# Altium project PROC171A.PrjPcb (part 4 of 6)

## Sheet PROC171_Ehernet_PHY_1.SchDoc
size 431 x 279 mm; Date: Not shown in title block; ApprovedBy: Not shown in title block; CheckedBy: Not shown in title block; Author: Not shown in title block; CompanyName: Not shown in title block; Engineer: Not shown in title block; Organization: Not shown in title block; Address1: Not shown in title block; Address2: Not shown in title block; Address3: Not shown in title block; Address4: Not shown in title block; DocumentNumber: 17; Revision: Use project parameter SCH_Rev; SheetNumber: 17; SheetTotal: 27; PageSetup: Record=PageOptions¦CenterHorizontal=True¦CenterVertical=True¦PrintScale=1.00¦XCorrection=1.00¦YCorrection=1.00¦PrintKind=0¦BorderSize=5000000¦LeftOffset=0¦BottomOffset=0¦Orientation=2¦PaperLength=1000¦PaperWidth=1000¦Scale=100¦PaperSource=15¦PrintQuality=600¦MediaType=1¦DitherType=10¦PaperKind=Letter¦PrintScaleMode=1
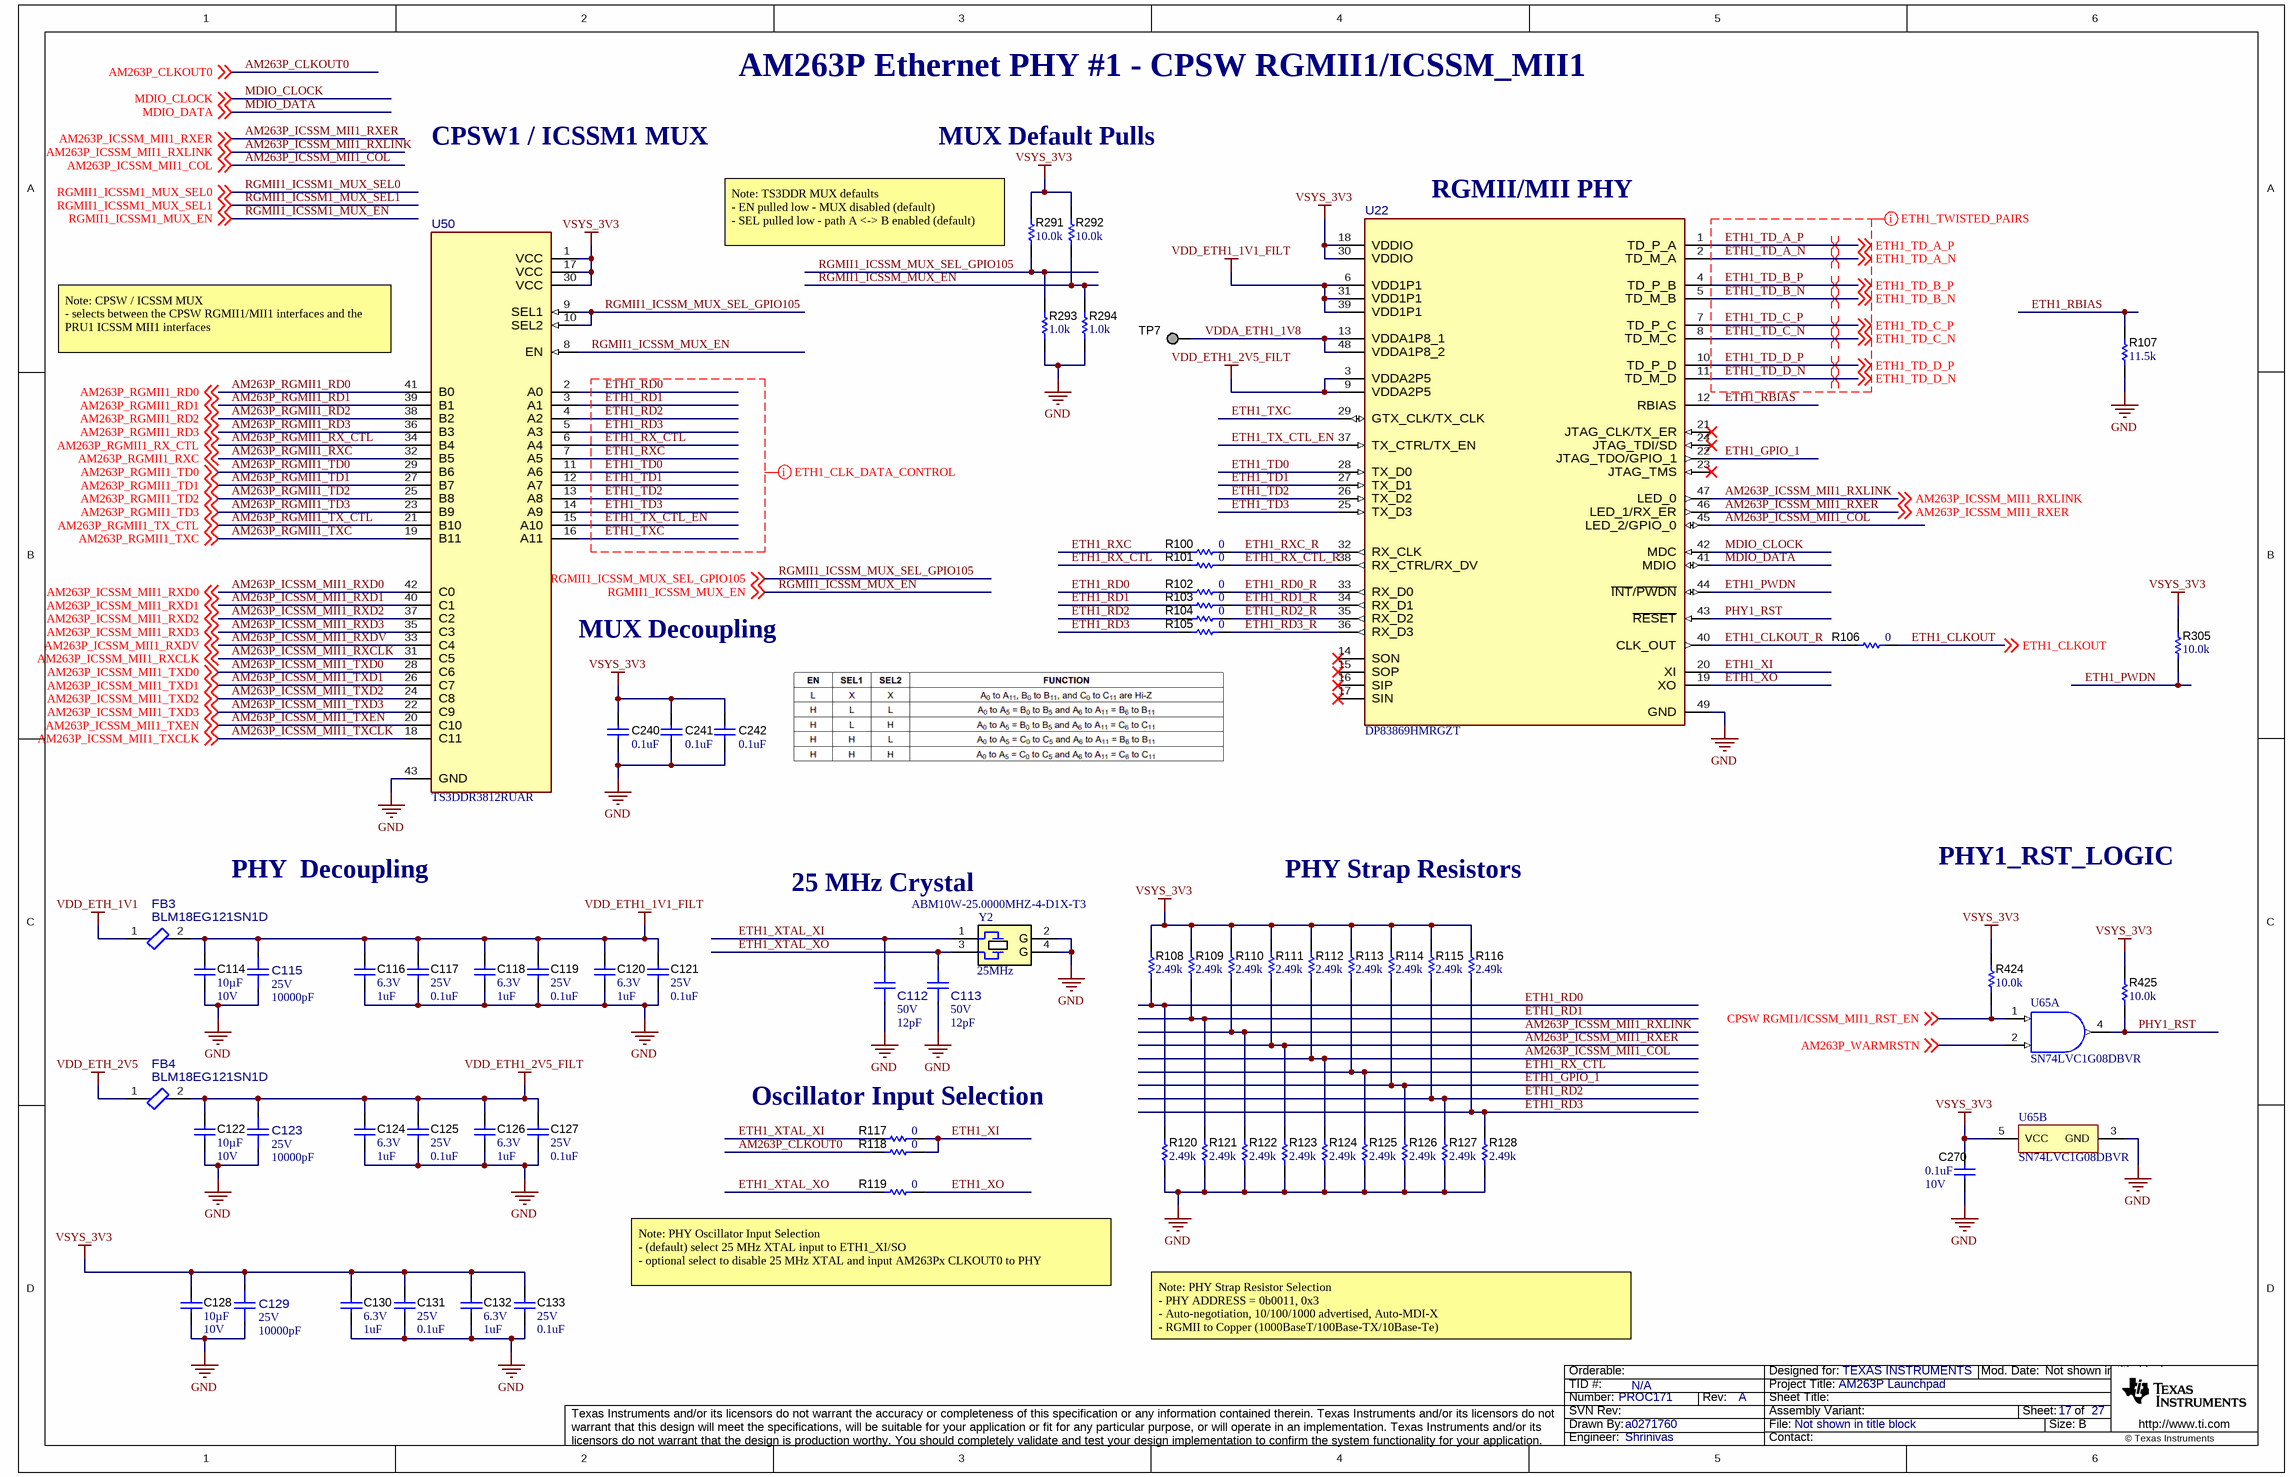
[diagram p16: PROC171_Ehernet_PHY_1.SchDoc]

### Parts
C112  VDC_V: 50V  ValueDisplayed: 12pF  [FP-GJM1555C1H120JB01D_0402-MFG]  (hidden comment: GJM1555C1H120JB01D)
C113  VDC_V: 50V  ValueDisplayed: 12pF  [FP-GJM1555C1H120JB01D_0402-MFG]  (hidden comment: GJM1555C1H120JB01D)
C114  Cap_F: 10µF  VDC_V: 10V  [0603]  (hidden comment: GRM188Z71A106MA73D)
C115  VDC_V: 25V  ValueDisplayed: 10000pF  [FP-GRM1555C1E103JE01D_0402-MFG]  (hidden comment: GRM1555C1E103JE01D)
C116  VDC_V: 6.3V  ValueDisplayed: 1uF  [0402]  (hidden comment: GRM155R70J105MA12D)
C117  VDC_V: 25V  ValueDisplayed: 0.1uF  [0402]  (hidden comment: GRM155R71E104KE14D)
C118  VDC_V: 6.3V  ValueDisplayed: 1uF  [0402]  (hidden comment: GRM155R70J105MA12D)
C119  VDC_V: 25V  ValueDisplayed: 0.1uF  [0402]  (hidden comment: GRM155R71E104KE14D)
C120  VDC_V: 6.3V  ValueDisplayed: 1uF  [0402]  (hidden comment: GRM155R70J105MA12D)
C121  VDC_V: 25V  ValueDisplayed: 0.1uF  [0402]  (hidden comment: GRM155R71E104KE14D)
C122  Cap_F: 10µF  VDC_V: 10V  [0603]  (hidden comment: GRM188Z71A106MA73D)
C123  VDC_V: 25V  ValueDisplayed: 10000pF  [FP-GRM1555C1E103JE01D_0402-MFG]  (hidden comment: GRM1555C1E103JE01D)
C124  VDC_V: 6.3V  ValueDisplayed: 1uF  [0402]  (hidden comment: GRM155R70J105MA12D)
C125  VDC_V: 25V  ValueDisplayed: 0.1uF  [0402]  (hidden comment: GRM155R71E104KE14D)
C126  VDC_V: 6.3V  ValueDisplayed: 1uF  [0402]  (hidden comment: GRM155R70J105MA12D)
C127  VDC_V: 25V  ValueDisplayed: 0.1uF  [0402]  (hidden comment: GRM155R71E104KE14D)
C128  Cap_F: 10µF  VDC_V: 10V  [0603]  (hidden comment: GRM188Z71A106MA73D)
C129  VDC_V: 25V  ValueDisplayed: 10000pF  [FP-GRM1555C1E103JE01D_0402-MFG]  (hidden comment: GRM1555C1E103JE01D)
C130  VDC_V: 6.3V  ValueDisplayed: 1uF  [0402]  (hidden comment: GRM155R70J105MA12D)
C131  VDC_V: 25V  ValueDisplayed: 0.1uF  [0402]  (hidden comment: GRM155R71E104KE14D)
C132  VDC_V: 6.3V  ValueDisplayed: 1uF  [0402]  (hidden comment: GRM155R70J105MA12D)
C133  VDC_V: 25V  ValueDisplayed: 0.1uF  [0402]  (hidden comment: GRM155R71E104KE14D)
C240  ValueDisplayed: 0.1uF  [0402]  (hidden comment: GRM155R71E104KE14D)
C241  ValueDisplayed: 0.1uF  [0402]  (hidden comment: GRM155R71E104KE14D)
C242  ValueDisplayed: 0.1uF  [0402]  (hidden comment: GRM155R71E104KE14D)
C270  VDC_V: 10V  ValueDisplayed: 0.1uF  [0402]  (hidden comment: 885012105010)
FB3  BLM18EG121SN1D  [FP-BLM18EG121SN1D_0603-MFG]
FB4  BLM18EG121SN1D  [FP-BLM18EG121SN1D_0603-MFG]
R100  ValueDisplayed: 0  [0402]  (hidden comment: ERJ-2GE0R00X)
R101  ValueDisplayed: 0  [0402]  (hidden comment: ERJ-2GE0R00X)
R102  ValueDisplayed: 0  [0402]  (hidden comment: ERJ-2GE0R00X)
R103  ValueDisplayed: 0  [0402]  (hidden comment: ERJ-2GE0R00X)
R104  ValueDisplayed: 0  [0402]  (hidden comment: ERJ-2GE0R00X)
R105  ValueDisplayed: 0  [0402]  (hidden comment: ERJ-2GE0R00X)
R106  ValueDisplayed: 0  [0402]  (hidden comment: ERJ-2GE0R00X)
R107  ValueDisplayed: 11.5k  [0402]  (hidden comment: ERJ-2RKF1152X)
R108  ValueDisplayed: 2.49k  [0402]  (hidden comment: CRCW04022K49FKED)
R109  ValueDisplayed: 2.49k  [0402]  (hidden comment: CRCW04022K49FKED)
R110  ValueDisplayed: 2.49k  [0402]  (hidden comment: CRCW04022K49FKED)
R111  ValueDisplayed: 2.49k  [0402]  (hidden comment: CRCW04022K49FKED)
R112  ValueDisplayed: 2.49k  [0402]  (hidden comment: CRCW04022K49FKED)
R113  ValueDisplayed: 2.49k  [0402]  (hidden comment: CRCW04022K49FKED)
R114  ValueDisplayed: 2.49k  [0402]  (hidden comment: CRCW04022K49FKED)
R115  ValueDisplayed: 2.49k  [0402]  (hidden comment: CRCW04022K49FKED)
R116  ValueDisplayed: 2.49k  [0402]  (hidden comment: CRCW04022K49FKED)
R117  ValueDisplayed: 0  [0402]  (hidden comment: ERJ-2GE0R00X)
R118  ValueDisplayed: 0  [0402]  (hidden comment: ERJ-2GE0R00X)
R119  ValueDisplayed: 0  [0402]  (hidden comment: ERJ-2GE0R00X)
R120  ValueDisplayed: 2.49k  [0402]  (hidden comment: CRCW04022K49FKED)
R121  ValueDisplayed: 2.49k  [0402]  (hidden comment: CRCW04022K49FKED)
R122  ValueDisplayed: 2.49k  [0402]  (hidden comment: CRCW04022K49FKED)
R123  ValueDisplayed: 2.49k  [0402]  (hidden comment: CRCW04022K49FKED)
R124  ValueDisplayed: 2.49k  [0402]  (hidden comment: CRCW04022K49FKED)
R125  ValueDisplayed: 2.49k  [0402]  (hidden comment: CRCW04022K49FKED)
R126  ValueDisplayed: 2.49k  [0402]  (hidden comment: CRCW04022K49FKED)
R127  ValueDisplayed: 2.49k  [0402]  (hidden comment: CRCW04022K49FKED)
R128  ValueDisplayed: 2.49k  [0402]  (hidden comment: CRCW04022K49FKED)
R291  ValueDisplayed: 10.0k  [0402]  (hidden comment: ERJ-2RKF1002X)
R292  ValueDisplayed: 10.0k  [0402]  (hidden comment: ERJ-2RKF1002X)
R293  ValueDisplayed: 1.0k  [0402]  (hidden comment: ERJ-2GEJ102X)
R294  ValueDisplayed: 1.0k  [0402]  (hidden comment: ERJ-2GEJ102X)
R305  ValueDisplayed: 10.0k  [0402]  (hidden comment: ERJ-2RKF1002X)
R424  ValueDisplayed: 10.0k  [0402]  (hidden comment: ERJ-2RKF1002X)
R425  ValueDisplayed: 10.0k  [0402L]  (hidden comment: CRCW040210K0FKED)
TP7  TESTPOINT  [TP_25MIL-SMT]  (value not drawn)  (no BOM)
U22  DP83869HMRGZT  [RGZ0048B-MFG]
U50  TS3DDR3812RUAR  [RUA0042A-MFG]
U65  SN74LVC1G08DBVR  [DBV0005A_N]  (parts A,B of 2)
Y2  Frequency_Fixed: 25MHz  [Abracon_ABM10W]  (hidden comment: ABM10W-25.0000MHZ-4-D1X-T3)

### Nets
GND: C112.1 C113.1 C114.2 C115.1 C116.2 C117.2 C118.2 C119.2 C120.2 C121.2 C122.2 C123.1 C124.2 C125.2 C126.2 C127.2 C128.2 C129.1 C130.2 C131.2 C132.2 C133.2 C240.1 C241.1 C242.1 C270.2 R107.1 R120.1 R121.1 R122.1 R123.1 R124.1 R125.1 R126.1 R127.1 R128.1 R293.1 R294.1 U22.49(GND) U50.43(GND) U65.3(GND) Y2.2(GND) Y2.4(GND)
VDD_ETH1_1V1_FILT: C114.1 C115.2 C116.1 C117.1 C118.1 C119.1 C120.1 C121.1 FB3.2 U22.6(VDD1P1) U22.31(VDD1P1) U22.39(VDD1P1)
VDD_ETH1_2V5_FILT: C122.1 C123.2 C124.1 C125.1 C126.1 C127.1 FB4.2 U22.3(VDDA2P5) U22.9(VDDA2P5)
VDD_ETH_1V1: FB3.1
VDD_ETH_2V5: FB4.1
VSYS_3V3: C128.1 C129.2 C130.1 C131.1 C132.1 C133.1 C240.2 C241.2 C242.2 C270.1 R108.2 R109.2 R110.2 R111.2 R112.2 R113.2 R114.2 R115.2 R116.2 R291.1 R292.1 R305.1 R424.1 R425.2 U22.18(VDDIO) U22.30(VDDIO) U50.1(VCC) U50.17(VCC) U50.30(VCC) U65.5(VCC)
AM263P_CLKOUT0: R118.1 ; off-sheet AM263P_CLKOUT0
AM263P_ICSSM_MII1_COL: R112.1 R124.2 U22.45(LED_2/GPIO_0) ; off-sheet AM263P_ICSSM_MII1_COL
AM263P_ICSSM_MII1_RXCLK: U50.31(C5) ; off-sheet AM263P_ICSSM_MII1_RXCLK
AM263P_ICSSM_MII1_RXD0: U50.42(C0) ; off-sheet AM263P_ICSSM_MII1_RXD0
AM263P_ICSSM_MII1_RXD1: U50.40(C1) ; off-sheet AM263P_ICSSM_MII1_RXD1
AM263P_ICSSM_MII1_RXD2: U50.37(C2) ; off-sheet AM263P_ICSSM_MII1_RXD2
AM263P_ICSSM_MII1_RXD3: U50.35(C3) ; off-sheet AM263P_ICSSM_MII1_RXD3
AM263P_ICSSM_MII1_RXDV: U50.33(C4) ; off-sheet AM263P_ICSSM_MII1_RXDV
AM263P_ICSSM_MII1_RXER: R111.1 R123.2 U22.46(LED_1/RX_ER) ; off-sheet AM263P_ICSSM_MII1_RXER
AM263P_ICSSM_MII1_RXLINK: R110.1 R122.2 U22.47(LED_0) ; off-sheet AM263P_ICSSM_MII1_RXLINK
AM263P_ICSSM_MII1_TXCLK: U50.18(C11) ; off-sheet AM263P_ICSSM_MII1_TXCLK
AM263P_ICSSM_MII1_TXD0: U50.28(C6) ; off-sheet AM263P_ICSSM_MII1_TXD0
AM263P_ICSSM_MII1_TXD1: U50.26(C7) ; off-sheet AM263P_ICSSM_MII1_TXD1
AM263P_ICSSM_MII1_TXD2: U50.24(C8) ; off-sheet AM263P_ICSSM_MII1_TXD2
AM263P_ICSSM_MII1_TXD3: U50.22(C9) ; off-sheet AM263P_ICSSM_MII1_TXD3
AM263P_ICSSM_MII1_TXEN: U50.20(C10) ; off-sheet AM263P_ICSSM_MII1_TXEN
AM263P_RGMII1_RD0: U50.41(B0) ; off-sheet AM263P_RGMII1_RD0
AM263P_RGMII1_RD1: U50.39(B1) ; off-sheet AM263P_RGMII1_RD1
AM263P_RGMII1_RD2: U50.38(B2) ; off-sheet AM263P_RGMII1_RD2
AM263P_RGMII1_RD3: U50.36(B3) ; off-sheet AM263P_RGMII1_RD3
AM263P_RGMII1_RX_CTL: U50.34(B4) ; off-sheet AM263P_RGMII1_RX_CTL
AM263P_RGMII1_RXC: U50.32(B5) ; off-sheet AM263P_RGMII1_RXC
AM263P_RGMII1_TD0: U50.29(B6) ; off-sheet AM263P_RGMII1_TD0
AM263P_RGMII1_TD1: U50.27(B7) ; off-sheet AM263P_RGMII1_TD1
AM263P_RGMII1_TD2: U50.25(B8) ; off-sheet AM263P_RGMII1_TD2
AM263P_RGMII1_TD3: U50.23(B9) ; off-sheet AM263P_RGMII1_TD3
AM263P_RGMII1_TX_CTL: U50.21(B10) ; off-sheet AM263P_RGMII1_TX_CTL
AM263P_RGMII1_TXC: U50.19(B11) ; off-sheet AM263P_RGMII1_TXC
AM263P_WARMRSTN: U65.2(B) ; off-sheet AM263P_WARMRSTN
CPSW RGMI1/ICSSM_MII1_RST_EN: R424.2 U65.1(A) ; off-sheet CPSW RGMI1/ICSSM_MII1_RST_EN
ETH1_CLKOUT: R106.2 ; off-sheet ETH1_CLKOUT
ETH1_CLKOUT_R: R106.1 U22.40(CLK_OUT)
ETH1_GPIO_1: R114.1 R126.2 U22.22(JTAG_TDO/GPIO_1)
ETH1_PWDN: R305.2 U22.44(~{INT}/~{PWDN})
ETH1_RBIAS: R107.2 U22.12(RBIAS)
ETH1_RD0: R102.1 R108.1 R120.2 U50.2(A0)
ETH1_RD0_R: R102.2 U22.33(RX_D0)
ETH1_RD1: R103.1 R109.1 R121.2 U50.3(A1)
ETH1_RD1_R: R103.2 U22.34(RX_D1)
ETH1_RD2: R104.1 R115.1 R127.2 U50.4(A2)
ETH1_RD2_R: R104.2 U22.35(RX_D2)
ETH1_RD3: R105.1 R116.1 R128.2 U50.5(A3)
ETH1_RD3_R: R105.2 U22.36(RX_D3)
ETH1_RX_CTL: R101.1 R113.1 R125.2 U50.6(A4)
ETH1_RX_CTL_R: R101.2 U22.38(RX_CTRL/RX_DV)
ETH1_RXC: R100.1 U50.7(A5)
ETH1_RXC_R: R100.2 U22.32(RX_CLK)
ETH1_TD0: U22.28(TX_D0) U50.11(A6)
ETH1_TD1: U22.27(TX_D1) U50.12(A7)
ETH1_TD2: U22.26(TX_D2) U50.13(A8)
ETH1_TD3: U22.25(TX_D3) U50.14(A9)
ETH1_TD_A_N: U22.2(TD_M_A) ; off-sheet ETH1_TD_A_N
ETH1_TD_A_P: U22.1(TD_P_A) ; off-sheet ETH1_TD_A_P
ETH1_TD_B_N: U22.5(TD_M_B) ; off-sheet ETH1_TD_B_N
ETH1_TD_B_P: U22.4(TD_P_B) ; off-sheet ETH1_TD_B_P
ETH1_TD_C_N: U22.8(TD_M_C) ; off-sheet ETH1_TD_C_N
ETH1_TD_C_P: U22.7(TD_P_C) ; off-sheet ETH1_TD_C_P
ETH1_TD_D_N: U22.11(TD_M_D) ; off-sheet ETH1_TD_D_N
ETH1_TD_D_P: U22.10(TD_P_D) ; off-sheet ETH1_TD_D_P
ETH1_TX_CTL_EN: U22.37(TX_CTRL/TX_EN) U50.15(A10)
ETH1_TXC: U22.29(GTX_CLK/TX_CLK) U50.16(A11)
ETH1_XI: R117.2 R118.2 U22.20(XI)
ETH1_XO: R119.2 U22.19(XO)
ETH1_XTAL_XI: C112.2 R117.1 Y2.1
ETH1_XTAL_XO: C113.2 R119.1 Y2.3
MDIO_CLOCK: U22.42(MDC) ; off-sheet MDIO_CLOCK
MDIO_DATA: U22.41(MDIO) ; off-sheet MDIO_DATA
PHY1_RST: R425.1 U22.43(~{RESET}) U65.4(Y)
RGMII1_ICSSM_MUX_EN: R292.2 R294.2 U50.8(EN) ; off-sheet RGMII1_ICSSM_MUX_EN
RGMII1_ICSSM_MUX_SEL_GPIO105: R291.2 R293.2 U50.9(SEL1) U50.10(SEL2) ; off-sheet RGMII1_ICSSM_MUX_SEL_GPIO105
VDDA_ETH1_1V8: TP7.1 U22.13(VDDA1P8_1) U22.48(VDDA1P8_2)

Not connected (* = marked no-connect by the designer): U22 14(SON)* 15(SOP)* 16(SIP)* 17(SIN)* 21(JTAG_CLK/TX_ER)* 23(JTAG_TMS)* 24(JTAG_TDI/SD)*

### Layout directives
differential pair: ETH1_TD_A_N, ETH1_TD_A_P, ETH1_TD_B_N, ETH1_TD_B_P, ETH1_TD_C_N, ETH1_TD_C_P, ETH1_TD_D_N, ETH1_TD_D_P
mark named ETH1_TWISTED_PAIRS: ETH1_TD_A_N, ETH1_TD_A_P, ETH1_TD_B_N, ETH1_TD_B_P, ETH1_TD_C_N, ETH1_TD_C_P, ETH1_TD_D_N, ETH1_TD_D_P
mark named ETH1_CLK_DATA_CONTROL: ETH1_RD0, ETH1_RD1, ETH1_RD2, ETH1_RD3, ETH1_RX_CTL, ETH1_RXC, ETH1_TD0, ETH1_TD1, ETH1_TD2, ETH1_TD3, ETH1_TX_CTL_EN, ETH1_TXC

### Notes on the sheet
- AM263P Ethernet PHY #1 - CPSW RGMII1/ICSSM_MII1
- CPSW1 / ICSSM1 MUX
- MUX Default Pulls
- (near U22) RGMII/MII PHY
- (near R291) Note: TS3DDR MUX defaults
  - EN pulled low - MUX disabled (default)
  - SEL pulled low - path A <-> B enabled (default)
- (near U50) Note: CPSW / ICSSM MUX
  - selects between the CPSW RGMII1/MII1 interfaces and the PRU1 ICSSM MII1 interfaces
- (near U50) MUX Decoupling
- PHY  Decoupling
- (near Y2) 25 MHz Crystal
- PHY Strap Resistors
- PHY1_RST_LOGIC
- Oscillator Input Selection
- (near R119) Note: PHY Oscillator Input Selection
  - (default) select 25 MHz XTAL input to ETH1_XI/SO
  - optional select to disable 25 MHz XTAL and input AM263Px CLKOUT0 to PHY
- Note: PHY Strap Resistor Selection
  - PHY ADDRESS = 0b0011, 0x3
  - Auto-negotiation, 10/100/1000 advertised, Auto-MDI-X
  - RGMII to Copper (1000BaseT/100Base-TX/10Base-Te)

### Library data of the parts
C112 C113 = CMP-0035228-1: Multi-Layer Ceramic Capacitor 12pF C0G  ±5% 0402 Paper T/R; Manufacturer: Murata; TempCo: 30ppm/°C; SizeZ_mm: 0.55mm; AEC Qualified: No
C114 C122 C128 = CMP-0007497-5: CAP, CERM, 10 uF, 10 V, +/- 20%, X7R, 0603; Manufacturer: MuRata; TaMin_C: -55°C; Polarized: N; SizeAreaWB_mm2: 4.68; Value1: Unknown; U/M: EA; Value: 10uF; TaMax_C: 125°C; SizeZ_mm: 1; SizeX_mm: 1.6; SizeY_mm: 0.8; SizeArea_mm2: 1.28; AEC Category: Q200
C115 C123 C129 = CMP-0035343-1: Chip Multilayer Ceramic Capacitors for General Purpose, 0402, 10000pF, C0G, 30ppm/°C, 5%, 25V; Manufacturer: Murata; Value: 10nF; SizeZ_mm: 0.65mm; AEC Qualified: No
C116 C118 C120 C124 C126 C130 C132 = CMP-0006624-2: CAP, CERM, 1 uF, 6.3 V, +/- 20%, X7R, 0402; Manufacturer: MuRata; TaMin_C: -55°C; Polarized: N; SizeAreaWB_mm2: 3; Value1: Unknown; U/M: EA; Value: 1uF; TaMax_C: 125°C; SizeZ_mm: 0.6; SizeX_mm: 1; SizeY_mm: 0.5; Cap_F: 1µF; AEC Category: Q200
C117 C119 C121 C125 C127 C131 C133 = CMP-0006659-2: CAP, CERM, 0.1 uF, 25 V, +/- 10%, X7R, 0402; Manufacturer: MuRata; TaMin_C: -55°C; Polarized: N; SizeAreaWB_mm2: 3; Value1: Unknown; U/M: EA; Value: 0.1uF; TaMax_C: 125°C; SizeZ_mm: 0.6; SizeX_mm: 1; SizeY_mm: 0.5; Cap_F: 100nF; AEC Category: Q200
C240-C242 = CMP-0006659-2: CAP, CERM, 0.1 uF, 25 V, +/- 10%, X7R, 0402; Manufacturer: MuRata; TaMin_C: -55°C; Polarized: N; SizeAreaWB_mm2: 3; U/M: EA; Value: 0.1uF; TaMax_C: 125°C; SizeZ_mm: 0.6; SizeX_mm: 1; SizeY_mm: 0.5; Value2: 25V; Cap_F: 100nF; AEC Category: Q200; Value1: Unknown
C270 = CMP-0006221-2: CAP, CERM, 0.1 uF, 10 V, +/- 20%, X5R, 0402; Manufacturer: Wurth Elektronik; TaMin_C: -55°C; Polarized: N; SizeAreaWB_mm2: 3; Value1: Unknown; U/M: EA; Value: 0.1uF; TaMax_C: 85°C; SizeZ_mm: 0.6; SizeX_mm: 1; SizeY_mm: 0.5; Cap_F: 100nF; AEC Category: Q200
FB3 FB4 = CMP-0089199-1: 120 Ohms @ 100MHz 1  Ferrite Bead 0603 (1608 Metric) 2A 40mOhm; Manufacturer: Murata; DCR_ohm: 60m; AEC Qualified: No; Tolerance_%: 25%; SizeZ_mm: 0.95mm; Impedance At Frequency: 120Ω @ 100MHz
R100-R106 R117-R119 = CMP-0026992-3: RES, 0, 5%, 0.1 W, AEC-Q200 Grade 0, 0402; Manufacturer: Panasonic; Power_W: 100mW; TempCo: 600 ppm/C; Value_Code: 0000; Value: 0; EIA_Code: E24; SizeX_mm: 1; SizeY_mm: 0.5; SizeZ_mm: 0.6; Value2: 0.1W; AEC Qualified: Y; VDC_V: 50V; AEC Category: Q200; SizeAreaWB_mm2: 3
R107 = CMP-0082348-1: RES, 11.5 k, 1%, 0.1 W, AEC-Q200 Grade 0, 0402; Manufacturer: Panasonic; Value_Code: 11k5; SizeAreaWB_mm2: 3; SizeArea_mm2: 0.5; AEC Qualified: Y; AEC Category: Q200; Value: 11.5k; SizeZ_mm: 0.6; EIA_Code: E96; TempCo: 100 ppm/C; AEC Grade: 0; Power_W: 100mW; Value2: 0.1W; SizeX_mm: 1
R108-R116 R120-R128 = CMP-0026237-2: RES, 2.49 k, 1%, 0.063 W, AEC-Q200 Grade 0, 0402; Manufacturer: Vishay-Dale; Power_W: 63mW; TempCo: 100 ppm/C; Value_Code: 2k49; Value: 2.49k; EIA_Code: E96; SizeX_mm: 1; SizeY_mm: 0.5; SizeZ_mm: 0.6; Value2: 0.063W; AEC Qualified: Y; VDC_V: 50V; AEC Category: Q200; AEC Grade: 0
R291 R292 R305 R424 = CMP-0026658-1: RES, 10.0 k, 1%, 0.1 W, 0402; Manufacturer: Panasonic; Power_W: 100mW; TempCo: 100 ppm/C; Value_Code: 10k0; U/M: EA; Value: 10.0k; EIA_Code: E96; Res_ohm: 10k; SizeX_mm: 1; SizeY_mm: 0.5; SizeZ_mm: 0.6; Value2: 0.1W; VDC_V: 50V; AEC Category: Q200
R293 R294 = CMP-0078193-1: RES, 1.0 k, 5%, 0.1 W, AEC-Q200 Grade 0, 0402; Manufacturer: Panasonic; Value_Code: 1k00; SizeArea_mm2: 0.5; AEC Qualified: Y; AEC Category: Q200; Res_ohm: 1k; Value: 1.0k; SizeZ_mm: 0.6; Green_REACh: Passed; EIA_Code: E24; TempCo: 200 ppm/C; AEC Grade: 0; Power_W: 100mW; VDC_V: 50V; Value2: 0.1W; Green_Lifecycle: Active; U/M: EA; SizeX_mm: 1
R425 = CMP-0025958-3: RES, 10.0 k, 1%, 0.063 W, AEC-Q200 Grade 0, 0402; Manufacturer: Vishay-Dale; Power_W: 63mW; TempCo: 100 ppm/C; Value_Code: 10k0; Value: 10.0k; EIA_Code: E96; Res_ohm: 10k; SizeX_mm: 1; SizeY_mm: 0.5; SizeZ_mm: 0.6; Value2: 0.063W; AEC Qualified: Y; VDC_V: 50V; AEC Category: Q200; AEC Grade: 0
TP7 = CMP-0078143-3: TEST POINT.  No entry in BOM.
U22 = CMP-0091377-1: 1/1 Transceiver Ethernet 48-VQFN (7x7); Manufacturer: Texas Instruments; TaMin_C: -40°C; SizeZ_mm: 1mm; TaMax_C: +125°C; Max Supply Voltage: 3.45V; Number Of Channels: 1; AEC Qualified: No; Data Rate: 1000Mbits/s; Min Supply Voltage: 990mV; Simplex Duplex: Full-Duplex; Standoff Height: 0mm
U50 = CMP-0093539-2: IC MUX/DEMUX DDR3 1:2 42WQFN; Manufacturer: Texas Instruments; TaMax_C: +85°C; TaMin_C: -40°C; On State Resistance: 8Ω; SizeZ_mm: 0.8mm; Min Supply Voltage: 3V; Standoff Height: 0mm; Max Supply Voltage: 3.6V; AEC Qualified: No; PositionCount: 12; -3Db Bandwith: 1.675GHz; Nominal Supply Current: 300uA; AEC Category: Q200
U65 = CMP-0051588-2: Single 2-Input Positive-AND Gate, DBV0005A, LARGE T&R; Manufacturer: Texas Instruments; Logic: True; ICC @ Nom Voltage(Max)(mA): 0.01; VCC(Min)(V): 1.65; Bits(#): 1; Rating: Catalog; Schmitt Trigger: No; Voltage(Nom)(V): 1.8,2.5,3.3,5; Output Drive (IOL/IOH)(Max)(mA): 32/-32; Gate Type: AND; tpd @ Nom Voltage(Max)(ns): 4.5,6,4,5; VCC(Max)(V): 5.5; Output Type: CMOS; F @ Nom Voltage(Max)(Mhz): 150; Input Type: CMOS/TTL; Technology Family: LVC; AEC Category: Q200; AEC Qualified: N; CompType: IC
Y2 = CMP-0084811-1: Crystal, 25 MHz, 10 ppm, 4 pF, SMD; Manufacturer: Abracon Corporation; Load Capacitance: 4 pF; TaMax_C: 85°C; SizeY_mm: 2.5; SizeAreaWB_mm2: 10.5; AEC Category: Q200; Frequency Stability: 20 ppm; SizeX_mm: 2; SizeArea_mm2: 5; SizeZ_mm: 0.6; AEC Qualified: N; TaMin_C: -40°C; Frequency Tolerance: 10 ppm

## Sheet PROC171_Ehernet_PHY_2.SchDoc
size 431 x 279 mm; Date: Not shown in title block; ApprovedBy: Not shown in title block; CheckedBy: Not shown in title block; Author: Not shown in title block; CompanyName: Not shown in title block; Engineer: Not shown in title block; Organization: Not shown in title block; Address1: Not shown in title block; Address2: Not shown in title block; Address3: Not shown in title block; Address4: Not shown in title block; DocumentNumber: 18; Revision: Use project parameter SCH_Rev; SheetNumber: 18; SheetTotal: 27; PageSetup: Record=PageOptions¦CenterHorizontal=True¦CenterVertical=True¦PrintScale=1.00¦XCorrection=1.00¦YCorrection=1.00¦PrintKind=0¦BorderSize=5000000¦LeftOffset=0¦BottomOffset=0¦Orientation=2¦PaperLength=1000¦PaperWidth=1000¦Scale=100¦PaperSource=15¦PrintQuality=600¦MediaType=1¦DitherType=10¦PaperKind=Letter¦PrintScaleMode=1
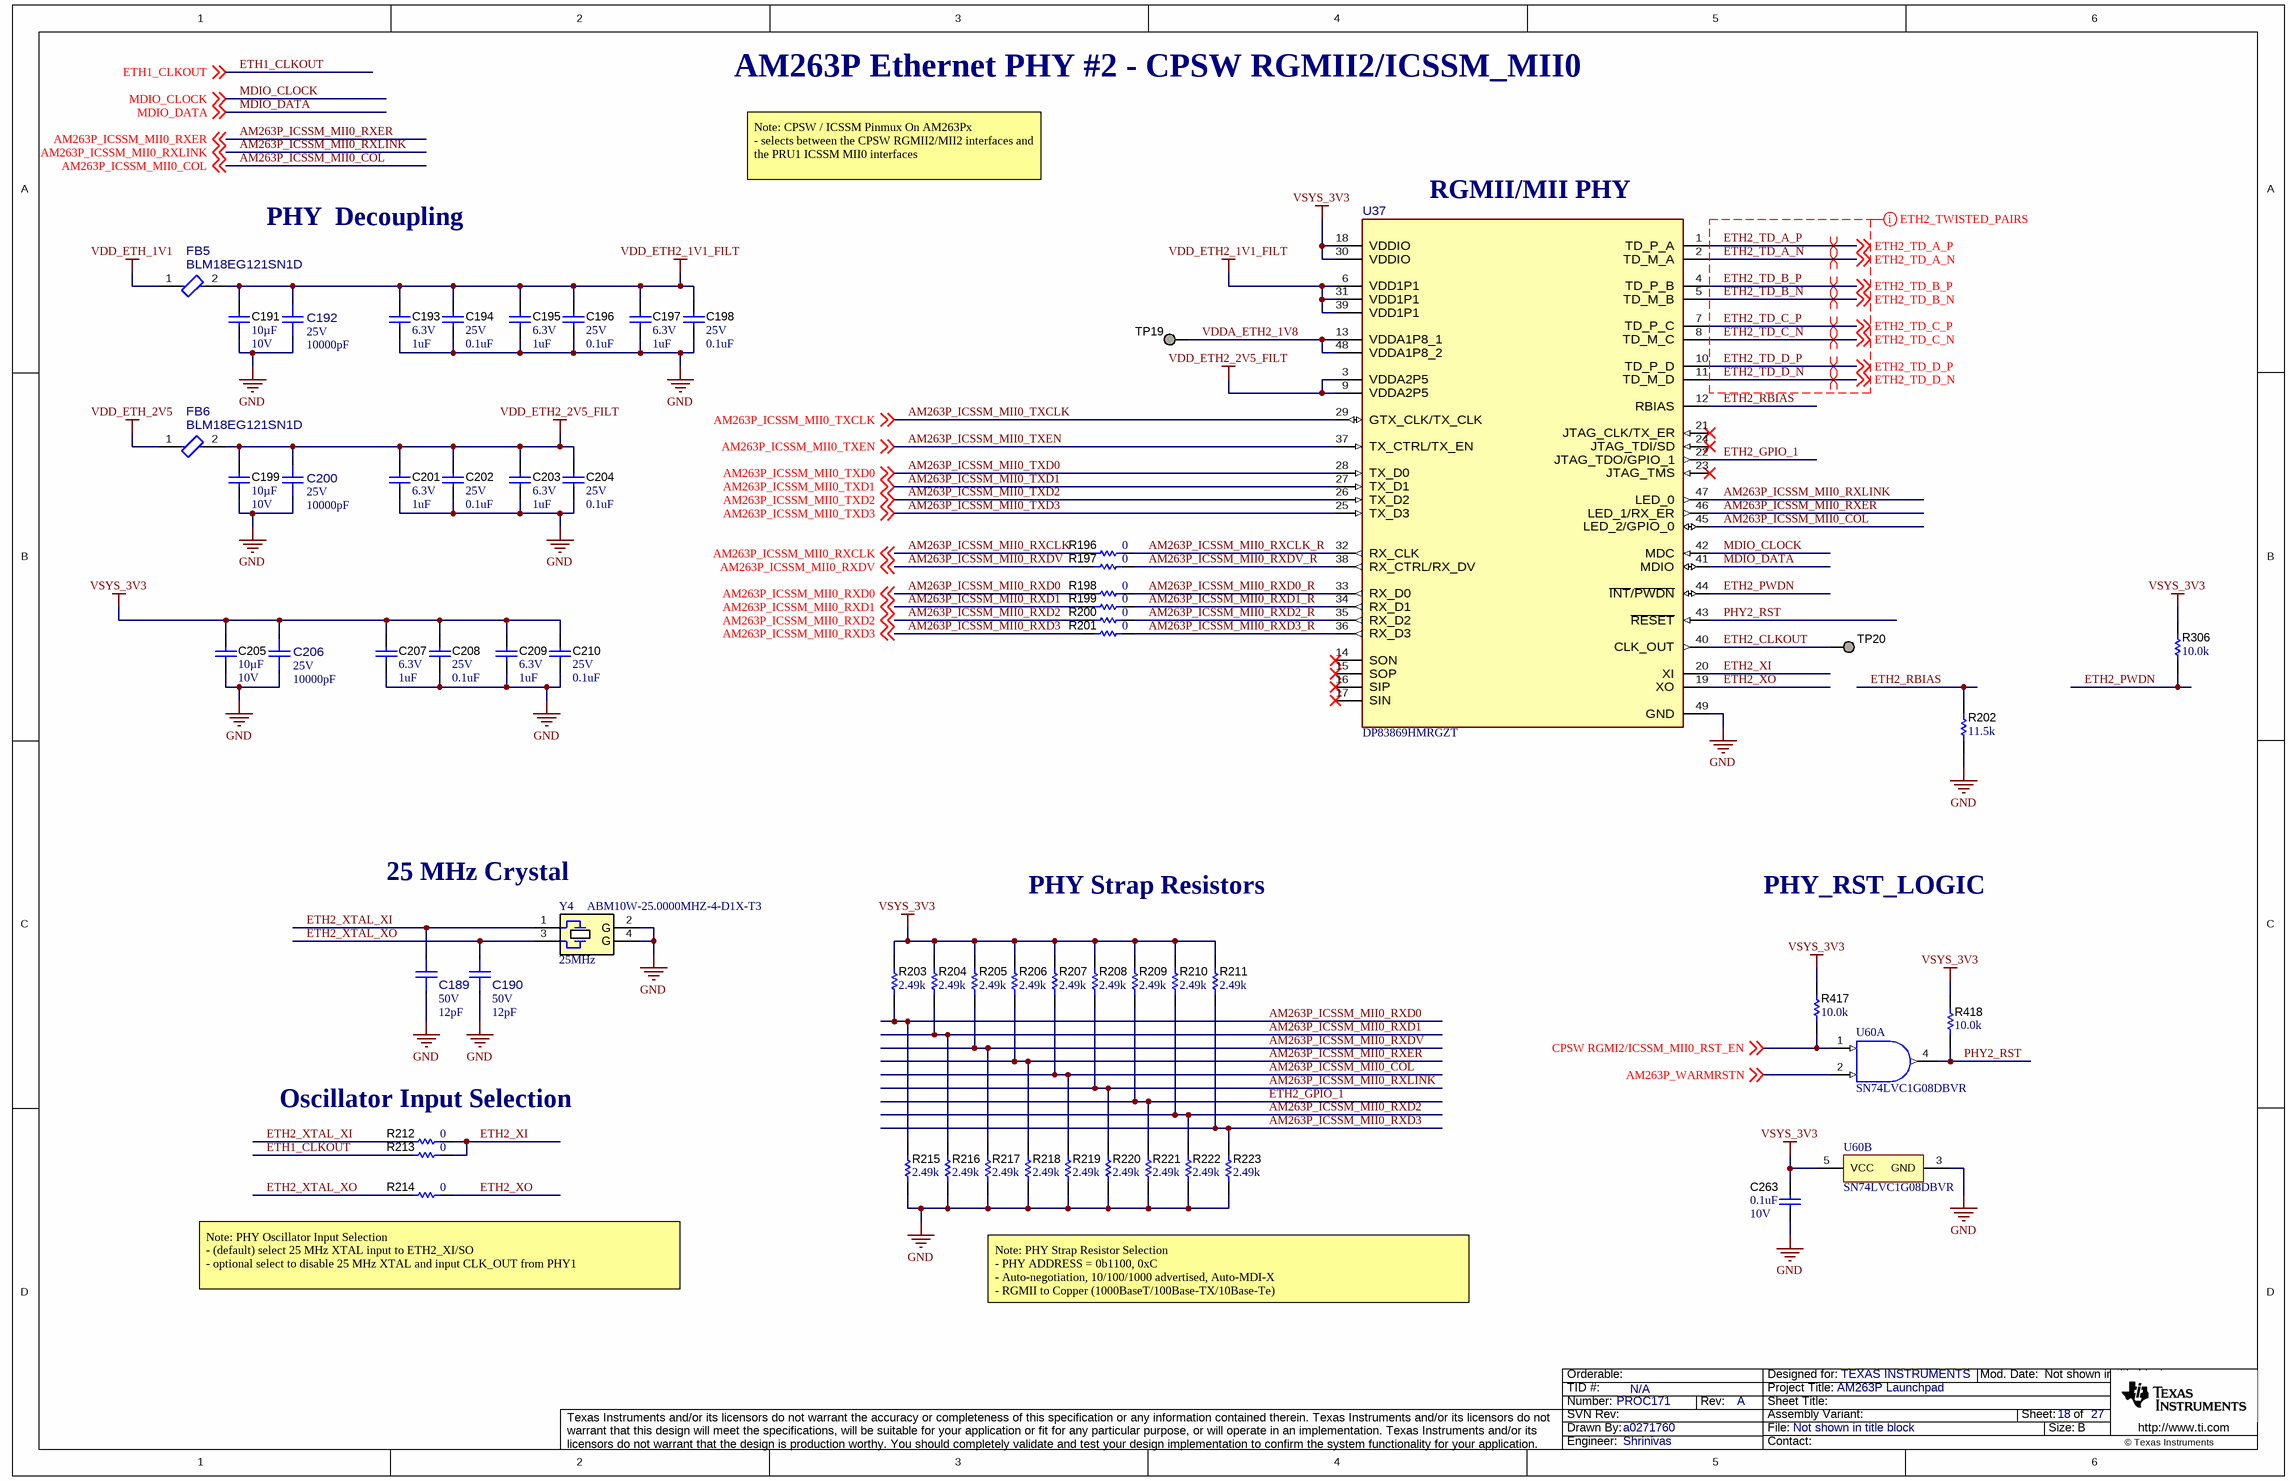
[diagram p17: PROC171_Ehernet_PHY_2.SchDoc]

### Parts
C189  VDC_V: 50V  ValueDisplayed: 12pF  [FP-GJM1555C1H120JB01D_0402-MFG]  (hidden comment: GJM1555C1H120JB01D)
C190  VDC_V: 50V  ValueDisplayed: 12pF  [FP-GJM1555C1H120JB01D_0402-MFG]  (hidden comment: GJM1555C1H120JB01D)
C191  Cap_F: 10µF  VDC_V: 10V  [0603]  (hidden comment: GRM188Z71A106MA73D)
C192  VDC_V: 25V  ValueDisplayed: 10000pF  [FP-GRM1555C1E103JE01D_0402-MFG]  (hidden comment: GRM1555C1E103JE01D)
C193  VDC_V: 6.3V  ValueDisplayed: 1uF  [0402]  (hidden comment: GRM155R70J105MA12D)
C194  VDC_V: 25V  ValueDisplayed: 0.1uF  [0402]  (hidden comment: GRM155R71E104KE14D)
C195  VDC_V: 6.3V  ValueDisplayed: 1uF  [0402]  (hidden comment: GRM155R70J105MA12D)
C196  VDC_V: 25V  ValueDisplayed: 0.1uF  [0402]  (hidden comment: GRM155R71E104KE14D)
C197  VDC_V: 6.3V  ValueDisplayed: 1uF  [0402]  (hidden comment: GRM155R70J105MA12D)
C198  VDC_V: 25V  ValueDisplayed: 0.1uF  [0402]  (hidden comment: GRM155R71E104KE14D)
C199  Cap_F: 10µF  VDC_V: 10V  [0603]  (hidden comment: GRM188Z71A106MA73D)
C200  VDC_V: 25V  ValueDisplayed: 10000pF  [FP-GRM1555C1E103JE01D_0402-MFG]  (hidden comment: GRM1555C1E103JE01D)
C201  VDC_V: 6.3V  ValueDisplayed: 1uF  [0402]  (hidden comment: GRM155R70J105MA12D)
C202  VDC_V: 25V  ValueDisplayed: 0.1uF  [0402]  (hidden comment: GRM155R71E104KE14D)
C203  VDC_V: 6.3V  ValueDisplayed: 1uF  [0402]  (hidden comment: GRM155R70J105MA12D)
C204  VDC_V: 25V  ValueDisplayed: 0.1uF  [0402]  (hidden comment: GRM155R71E104KE14D)
C205  Cap_F: 10µF  VDC_V: 10V  [0603]  (hidden comment: GRM188Z71A106MA73D)
C206  VDC_V: 25V  ValueDisplayed: 10000pF  [FP-GRM1555C1E103JE01D_0402-MFG]  (hidden comment: GRM1555C1E103JE01D)
C207  VDC_V: 6.3V  ValueDisplayed: 1uF  [0402]  (hidden comment: GRM155R70J105MA12D)
C208  VDC_V: 25V  ValueDisplayed: 0.1uF  [0402]  (hidden comment: GRM155R71E104KE14D)
C209  VDC_V: 6.3V  ValueDisplayed: 1uF  [0402]  (hidden comment: GRM155R70J105MA12D)
C210  VDC_V: 25V  ValueDisplayed: 0.1uF  [0402]  (hidden comment: GRM155R71E104KE14D)
C263  VDC_V: 10V  ValueDisplayed: 0.1uF  [0402]  (hidden comment: 885012105010)
FB5  BLM18EG121SN1D  [FP-BLM18EG121SN1D_0603-MFG]
FB6  BLM18EG121SN1D  [FP-BLM18EG121SN1D_0603-MFG]
R196  ValueDisplayed: 0  [0402]  (hidden comment: ERJ-2GE0R00X)
R197  ValueDisplayed: 0  [0402]  (hidden comment: ERJ-2GE0R00X)
R198  ValueDisplayed: 0  [0402]  (hidden comment: ERJ-2GE0R00X)
R199  ValueDisplayed: 0  [0402]  (hidden comment: ERJ-2GE0R00X)
R200  ValueDisplayed: 0  [0402]  (hidden comment: ERJ-2GE0R00X)
R201  ValueDisplayed: 0  [0402]  (hidden comment: ERJ-2GE0R00X)
R202  ValueDisplayed: 11.5k  [0402]  (hidden comment: ERJ-2RKF1152X)
R203  ValueDisplayed: 2.49k  [0402]  (hidden comment: CRCW04022K49FKED)
R204  ValueDisplayed: 2.49k  [0402]  (hidden comment: CRCW04022K49FKED)
R205  ValueDisplayed: 2.49k  [0402]  (hidden comment: CRCW04022K49FKED)
R206  ValueDisplayed: 2.49k  [0402]  (hidden comment: CRCW04022K49FKED)
R207  ValueDisplayed: 2.49k  [0402]  (hidden comment: CRCW04022K49FKED)
R208  ValueDisplayed: 2.49k  [0402]  (hidden comment: CRCW04022K49FKED)
R209  ValueDisplayed: 2.49k  [0402]  (hidden comment: CRCW04022K49FKED)
R210  ValueDisplayed: 2.49k  [0402]  (hidden comment: CRCW04022K49FKED)
R211  ValueDisplayed: 2.49k  [0402]  (hidden comment: CRCW04022K49FKED)
R212  ValueDisplayed: 0  [0402]  (hidden comment: ERJ-2GE0R00X)
R213  ValueDisplayed: 0  [0402]  (hidden comment: ERJ-2GE0R00X)
R214  ValueDisplayed: 0  [0402]  (hidden comment: ERJ-2GE0R00X)
R215  ValueDisplayed: 2.49k  [0402]  (hidden comment: CRCW04022K49FKED)
R216  ValueDisplayed: 2.49k  [0402]  (hidden comment: CRCW04022K49FKED)
R217  ValueDisplayed: 2.49k  [0402]  (hidden comment: CRCW04022K49FKED)
R218  ValueDisplayed: 2.49k  [0402]  (hidden comment: CRCW04022K49FKED)
R219  ValueDisplayed: 2.49k  [0402]  (hidden comment: CRCW04022K49FKED)
R220  ValueDisplayed: 2.49k  [0402]  (hidden comment: CRCW04022K49FKED)
R221  ValueDisplayed: 2.49k  [0402]  (hidden comment: CRCW04022K49FKED)
R222  ValueDisplayed: 2.49k  [0402]  (hidden comment: CRCW04022K49FKED)
R223  ValueDisplayed: 2.49k  [0402]  (hidden comment: CRCW04022K49FKED)
R306  ValueDisplayed: 10.0k  [0402]  (hidden comment: ERJ-2RKF1002X)
R417  ValueDisplayed: 10.0k  [0402]  (hidden comment: ERJ-2RKF1002X)
R418  ValueDisplayed: 10.0k  [0402L]  (hidden comment: CRCW040210K0FKED)
TP19  TESTPOINT  [TP_25MIL-SMT]  (value not drawn)  (no BOM)
TP20  TESTPOINT  [TP_25MIL-SMT]  (value not drawn)  (no BOM)
U37  DP83869HMRGZT  [RGZ0048B-MFG]
U60  SN74LVC1G08DBVR  [DBV0005A_N]  (parts A,B of 2)
Y4  Frequency_Fixed: 25MHz  [Abracon_ABM10W]  (hidden comment: ABM10W-25.0000MHZ-4-D1X-T3)

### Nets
GND: C189.1 C190.1 C191.2 C192.1 C193.2 C194.2 C195.2 C196.2 C197.2 C198.2 C199.2 C200.1 C201.2 C202.2 C203.2 C204.2 C205.2 C206.1 C207.2 C208.2 C209.2 C210.2 C263.2 R202.1 R215.1 R216.1 R217.1 R218.1 R219.1 R220.1 R221.1 R222.1 R223.1 U37.49(GND) U60.3(GND) Y4.2(GND) Y4.4(GND)
VDD_ETH2_1V1_FILT: C191.1 C192.2 C193.1 C194.1 C195.1 C196.1 C197.1 C198.1 FB5.2 U37.6(VDD1P1) U37.31(VDD1P1) U37.39(VDD1P1)
VDD_ETH2_2V5_FILT: C199.1 C200.2 C201.1 C202.1 C203.1 C204.1 FB6.2 U37.3(VDDA2P5) U37.9(VDDA2P5)
VDD_ETH_1V1: FB5.1
VDD_ETH_2V5: FB6.1
VSYS_3V3: C205.1 C206.2 C207.1 C208.1 C209.1 C210.1 C263.1 R203.2 R204.2 R205.2 R206.2 R207.2 R208.2 R209.2 R210.2 R211.2 R306.1 R417.1 R418.2 U37.18(VDDIO) U37.30(VDDIO) U60.5(VCC)
AM263P_ICSSM_MII0_COL: R207.1 R219.2 U37.45(LED_2/GPIO_0) ; off-sheet AM263P_ICSSM_MII0_COL
AM263P_ICSSM_MII0_RXCLK: R196.1 ; off-sheet AM263P_ICSSM_MII0_RXCLK
AM263P_ICSSM_MII0_RXCLK_R: R196.2 U37.32(RX_CLK)
AM263P_ICSSM_MII0_RXD0: R198.1 R203.1 R215.2 ; off-sheet AM263P_ICSSM_MII0_RXD0
AM263P_ICSSM_MII0_RXD0_R: R198.2 U37.33(RX_D0)
AM263P_ICSSM_MII0_RXD1: R199.1 R204.1 R216.2 ; off-sheet AM263P_ICSSM_MII0_RXD1
AM263P_ICSSM_MII0_RXD1_R: R199.2 U37.34(RX_D1)
AM263P_ICSSM_MII0_RXD2: R200.1 R210.1 R222.2 ; off-sheet AM263P_ICSSM_MII0_RXD2
AM263P_ICSSM_MII0_RXD2_R: R200.2 U37.35(RX_D2)
AM263P_ICSSM_MII0_RXD3: R201.1 R211.1 R223.2 ; off-sheet AM263P_ICSSM_MII0_RXD3
AM263P_ICSSM_MII0_RXD3_R: R201.2 U37.36(RX_D3)
AM263P_ICSSM_MII0_RXDV: R197.1 R205.1 R217.2 ; off-sheet AM263P_ICSSM_MII0_RXDV
AM263P_ICSSM_MII0_RXDV_R: R197.2 U37.38(RX_CTRL/RX_DV)
AM263P_ICSSM_MII0_RXER: R206.1 R218.2 U37.46(LED_1/RX_ER) ; off-sheet AM263P_ICSSM_MII0_RXER
AM263P_ICSSM_MII0_RXLINK: R208.1 R220.2 U37.47(LED_0) ; off-sheet AM263P_ICSSM_MII0_RXLINK
AM263P_ICSSM_MII0_TXCLK: U37.29(GTX_CLK/TX_CLK) ; off-sheet AM263P_ICSSM_MII0_TXCLK
AM263P_ICSSM_MII0_TXD0: U37.28(TX_D0) ; off-sheet AM263P_ICSSM_MII0_TXD0
AM263P_ICSSM_MII0_TXD1: U37.27(TX_D1) ; off-sheet AM263P_ICSSM_MII0_TXD1
AM263P_ICSSM_MII0_TXD2: U37.26(TX_D2) ; off-sheet AM263P_ICSSM_MII0_TXD2
AM263P_ICSSM_MII0_TXD3: U37.25(TX_D3) ; off-sheet AM263P_ICSSM_MII0_TXD3
AM263P_ICSSM_MII0_TXEN: U37.37(TX_CTRL/TX_EN) ; off-sheet AM263P_ICSSM_MII0_TXEN
AM263P_WARMRSTN: U60.2(B) ; off-sheet AM263P_WARMRSTN
CPSW RGMI2/ICSSM_MII0_RST_EN: R417.2 U60.1(A) ; off-sheet CPSW RGMI2/ICSSM_MII0_RST_EN
ETH1_CLKOUT: R213.1 ; off-sheet ETH1_CLKOUT
ETH2_CLKOUT: TP20.1 U37.40(CLK_OUT)
ETH2_GPIO_1: R209.1 R221.2 U37.22(JTAG_TDO/GPIO_1)
ETH2_PWDN: R306.2 U37.44(~{INT}/~{PWDN})
ETH2_RBIAS: R202.2 U37.12(RBIAS)
ETH2_TD_A_N: U37.2(TD_M_A) ; off-sheet ETH2_TD_A_N
ETH2_TD_A_P: U37.1(TD_P_A) ; off-sheet ETH2_TD_A_P
ETH2_TD_B_N: U37.5(TD_M_B) ; off-sheet ETH2_TD_B_N
ETH2_TD_B_P: U37.4(TD_P_B) ; off-sheet ETH2_TD_B_P
ETH2_TD_C_N: U37.8(TD_M_C) ; off-sheet ETH2_TD_C_N
ETH2_TD_C_P: U37.7(TD_P_C) ; off-sheet ETH2_TD_C_P
ETH2_TD_D_N: U37.11(TD_M_D) ; off-sheet ETH2_TD_D_N
ETH2_TD_D_P: U37.10(TD_P_D) ; off-sheet ETH2_TD_D_P
ETH2_XI: R212.2 R213.2 U37.20(XI)
ETH2_XO: R214.2 U37.19(XO)
ETH2_XTAL_XI: C189.2 R212.1 Y4.1
ETH2_XTAL_XO: C190.2 R214.1 Y4.3
MDIO_CLOCK: U37.42(MDC) ; off-sheet MDIO_CLOCK
MDIO_DATA: U37.41(MDIO) ; off-sheet MDIO_DATA
PHY2_RST: R418.1 U37.43(~{RESET}) U60.4(Y)
VDDA_ETH2_1V8: TP19.1 U37.13(VDDA1P8_1) U37.48(VDDA1P8_2)

Not connected (* = marked no-connect by the designer): U37 14(SON)* 15(SOP)* 16(SIP)* 17(SIN)* 21(JTAG_CLK/TX_ER)* 23(JTAG_TMS)* 24(JTAG_TDI/SD)*

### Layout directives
differential pair: ETH2_TD_A_N, ETH2_TD_A_P, ETH2_TD_B_N, ETH2_TD_B_P, ETH2_TD_C_N, ETH2_TD_C_P, ETH2_TD_D_N, ETH2_TD_D_P
mark named ETH2_TWISTED_PAIRS: ETH2_TD_A_N, ETH2_TD_A_P, ETH2_TD_B_N, ETH2_TD_B_P, ETH2_TD_C_N, ETH2_TD_C_P, ETH2_TD_D_N, ETH2_TD_D_P

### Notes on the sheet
- AM263P Ethernet PHY #2 - CPSW RGMII2/ICSSM_MII0
- PHY  Decoupling
- Note: CPSW / ICSSM Pinmux On AM263Px
  - selects between the CPSW RGMII2/MII2 interfaces and the PRU1 ICSSM MII0 interfaces
- (near U37) RGMII/MII PHY
- (near Y4) 25 MHz Crystal
- PHY Strap Resistors
- PHY_RST_LOGIC
- Oscillator Input Selection
- (near R214) Note: PHY Oscillator Input Selection
  - (default) select 25 MHz XTAL input to ETH2_XI/SO
  - optional select to disable 25 MHz XTAL and input CLK_OUT from PHY1
- Note: PHY Strap Resistor Selection
  - PHY ADDRESS = 0b1100, 0xC
  - Auto-negotiation, 10/100/1000 advertised, Auto-MDI-X
  - RGMII to Copper (1000BaseT/100Base-TX/10Base-Te)

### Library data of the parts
C189 C190 = CMP-0035228-1: as C112 on sheet PROC171_Ehernet_PHY_1
C191 C199 C205 = CMP-0007497-5: as C114 on sheet PROC171_Ehernet_PHY_1
C192 C200 C206 = CMP-0035343-1: as C115 on sheet PROC171_Ehernet_PHY_1
C193 C195 C197 C201 C203 C207 C209 = CMP-0006624-2: as C116 on sheet PROC171_Ehernet_PHY_1
C194 C196 C198 C202 C204 C208 C210 = CMP-0006659-2: as C117 on sheet PROC171_Ehernet_PHY_1
C263 = CMP-0006221-2: as C270 on sheet PROC171_Ehernet_PHY_1
FB5 FB6 = CMP-0089199-1: as FB3 on sheet PROC171_Ehernet_PHY_1
R196-R201 R212-R214 = CMP-0026992-3: as R100-R106 on sheet PROC171_Ehernet_PHY_1
R202 = CMP-0082348-1: as R107 on sheet PROC171_Ehernet_PHY_1
R203-R211 R215-R223 = CMP-0026237-2: as R108-R116 on sheet PROC171_Ehernet_PHY_1
R306 R417 = CMP-0026658-1: as R291 on sheet PROC171_Ehernet_PHY_1
R418 = CMP-0025958-3: as R425 on sheet PROC171_Ehernet_PHY_1
TP19 TP20 = CMP-0078143-3: TEST POINT.  No entry in BOM.
U37 = CMP-0091377-1: as U22 on sheet PROC171_Ehernet_PHY_1
U60 = CMP-0051588-2: as U65 on sheet PROC171_Ehernet_PHY_1
Y4 = CMP-0084811-1: as Y2 on sheet PROC171_Ehernet_PHY_1

## Sheet PROC171_Ehernet_RJ45_1.SchDoc
size 431 x 279 mm; Date: Not shown in title block; ApprovedBy: Not shown in title block; CheckedBy: Not shown in title block; Author: Not shown in title block; CompanyName: Not shown in title block; Engineer: Not shown in title block; Organization: Not shown in title block; Address1: Not shown in title block; Address2: Not shown in title block; Address3: Not shown in title block; Address4: Not shown in title block; DocumentNumber: 19; Revision: Use project parameter SCH_Rev; SheetNumber: 19; SheetTotal: 27; PageSetup: Record=PageOptions¦CenterHorizontal=True¦CenterVertical=True¦PrintScale=1.00¦XCorrection=1.00¦YCorrection=1.00¦PrintKind=0¦BorderSize=5000000¦LeftOffset=0¦BottomOffset=0¦Orientation=2¦PaperLength=1000¦PaperWidth=1000¦Scale=100¦PaperSource=15¦PrintQuality=600¦MediaType=1¦DitherType=10¦PaperKind=Letter¦PrintScaleMode=1
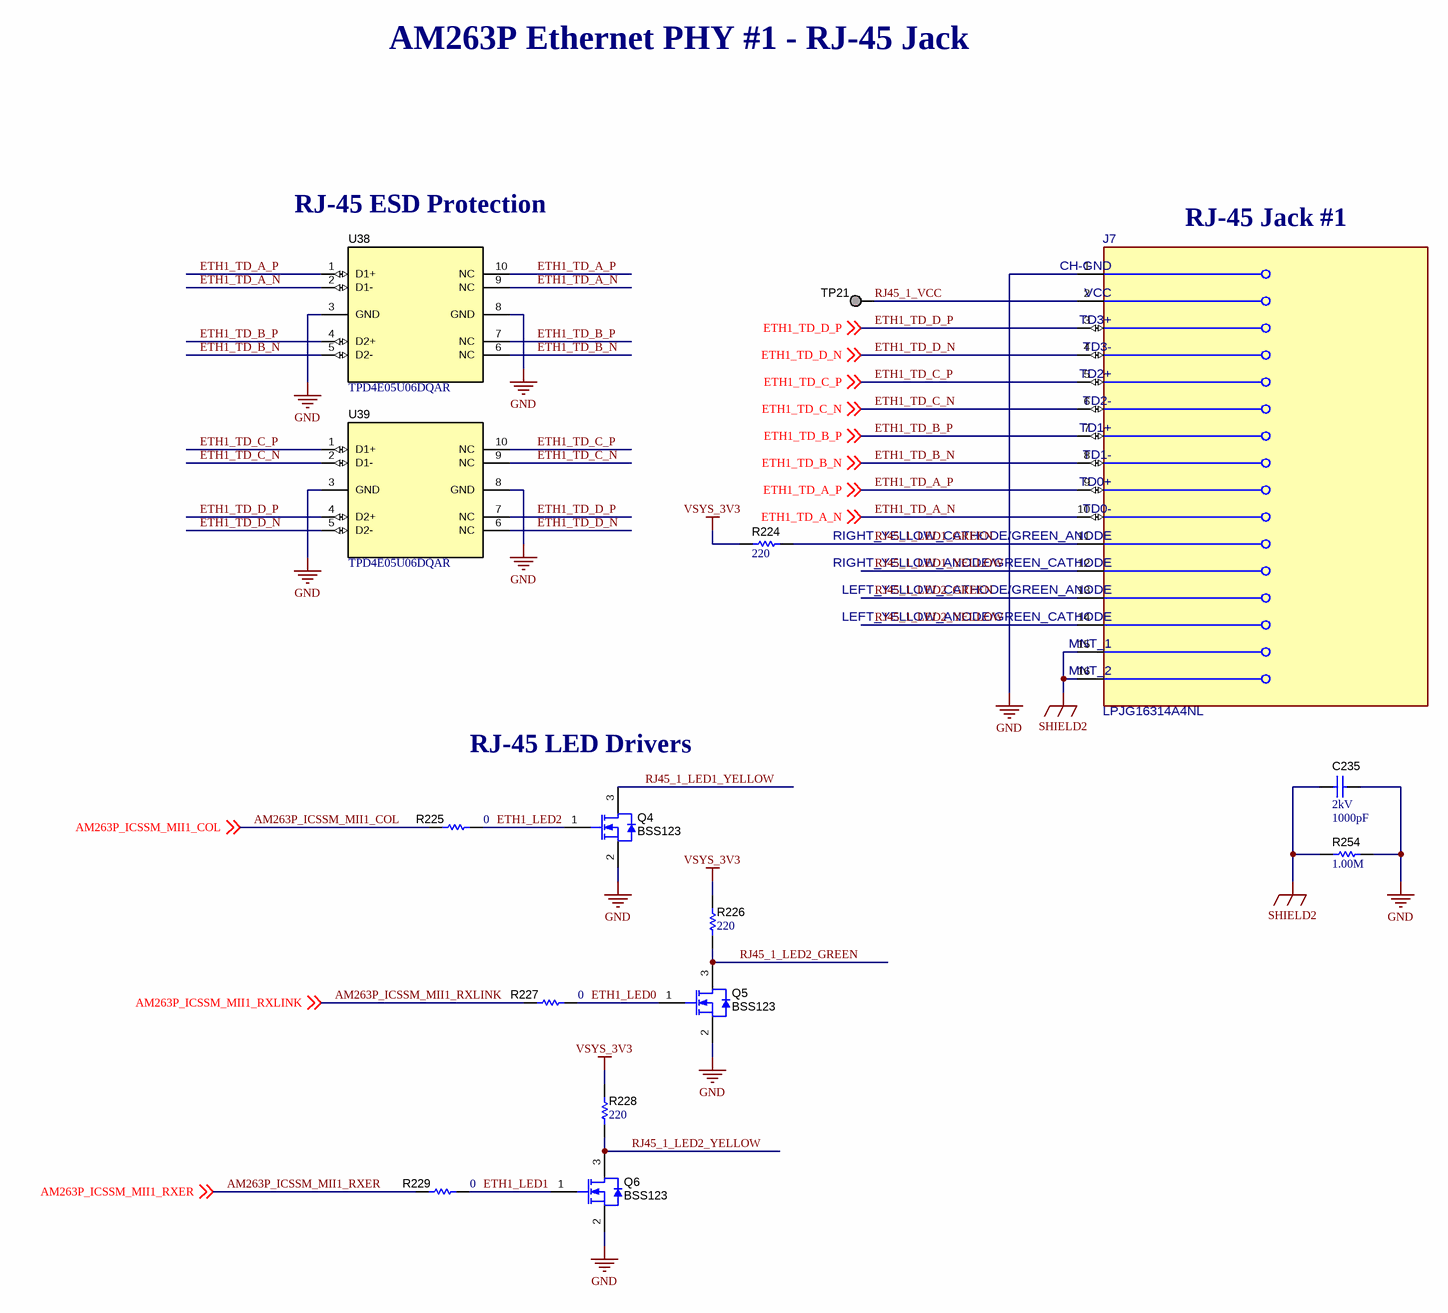
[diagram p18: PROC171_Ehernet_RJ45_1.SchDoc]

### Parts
C235  VDC_V: 2kV  ValueDisplayed: 1000pF  [1808]  (hidden comment: GR442QR73D102KW01L)
J7  LPJG16314A4NL  [FP-LPJG16314A4NL_CONN_RJ45-MFG]
Q4  BSS123  [SOT-23]
Q5  BSS123  [SOT-23]
Q6  BSS123  [SOT-23]
R224  ValueDisplayed: 220  [0402]  (hidden comment: CRCW0402220RJNED)
R225  ValueDisplayed: 0  [0402L]  (hidden comment: ERJ-2GE0R00X)
R226  ValueDisplayed: 220  [0402]  (hidden comment: CRCW0402220RJNED)
R227  ValueDisplayed: 0  [0402L]  (hidden comment: ERJ-2GE0R00X)
R228  ValueDisplayed: 220  [0402]  (hidden comment: CRCW0402220RJNED)
R229  ValueDisplayed: 0  [0402L]  (hidden comment: ERJ-2GE0R00X)
R254  ValueDisplayed: 1.00M  [0805_HV]  (hidden comment: ERJ-6ENF1004V)
TP21  TESTPOINT  [TP_25MIL-SMT]  (value not drawn)  (no BOM)
U38  TPD4E05U06DQAR  [DQA0010A]
U39  TPD4E05U06DQAR  [DQA0010A]

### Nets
GND: C235.1 J7.1(CH-GND) Q4.2(S) Q5.2(S) Q6.2(S) R254.2 U38.3(GND) U38.8(GND) U39.3(GND) U39.8(GND)
SHIELD2: C235.2 J7.15(MNT_1) J7.16(MNT_2) R254.1
VSYS_3V3: R224.1 R226.2 R228.2
AM263P_ICSSM_MII1_COL: R225.2 ; off-sheet AM263P_ICSSM_MII1_COL
AM263P_ICSSM_MII1_RXER: R229.2 ; off-sheet AM263P_ICSSM_MII1_RXER
AM263P_ICSSM_MII1_RXLINK: R227.2 ; off-sheet AM263P_ICSSM_MII1_RXLINK
ETH1_LED0: Q5.1(G) R227.1
ETH1_LED1: Q6.1(G) R229.1
ETH1_LED2: Q4.1(G) R225.1
ETH1_TD_A_N: J7.10(TD0-) U38.2(D1-) U38.9(NC) ; off-sheet ETH1_TD_A_N
ETH1_TD_A_P: J7.9(TD0+) U38.1(D1+) U38.10(NC) ; off-sheet ETH1_TD_A_P
ETH1_TD_B_N: J7.8(TD1-) U38.5(D2-) U38.6(NC) ; off-sheet ETH1_TD_B_N
ETH1_TD_B_P: J7.7(TD1+) U38.4(D2+) U38.7(NC) ; off-sheet ETH1_TD_B_P
ETH1_TD_C_N: J7.6(TD2-) U39.2(D1-) U39.9(NC) ; off-sheet ETH1_TD_C_N
ETH1_TD_C_P: J7.5(TD2+) U39.1(D1+) U39.10(NC) ; off-sheet ETH1_TD_C_P
ETH1_TD_D_N: J7.4(TD3-) U39.5(D2-) U39.6(NC) ; off-sheet ETH1_TD_D_N
ETH1_TD_D_P: J7.3(TD3+) U39.4(D2+) U39.7(NC) ; off-sheet ETH1_TD_D_P
RJ45_1_LED1_GREEN: J7.11(RIGHT_YELLOW_CATHODE/GREEN_ANODE) R224.2
RJ45_1_LED1_YELLOW: J7.12(RIGHT_YELLOW_ANODE/GREEN_CATHODE) Q4.3(D)
RJ45_1_LED2_GREEN: J7.13(LEFT_YELLOW_CATHODE/GREEN_ANODE) Q5.3(D) R226.1
RJ45_1_LED2_YELLOW: J7.14(LEFT_YELLOW_ANODE/GREEN_CATHODE) Q6.3(D) R228.1
RJ45_1_VCC: J7.2(VCC) TP21.1

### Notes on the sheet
- AM263P Ethernet PHY #1 - RJ-45 Jack
- RJ-45 ESD Protection
- RJ-45 Jack #1
- RJ-45 LED Drivers

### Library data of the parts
C235 = CMP-0009436-2: CAP, CERM, 1000 pF, 2000 V, +/- 10%, X7R, 1808; Manufacturer: MuRata; TaMin_C: -55°C; Polarized: N; SizeAreaWB_mm2: 16.5; Value1: Unknown; U/M: EA; Value: 1000pF; TaMax_C: 125°C; SizeZ_mm: 2.03; SizeX_mm: 4.5; SizeY_mm: 2; Value2: 2000V; SizeArea_mm2: 9; Cap_F: 1nF; AEC Category: Q200
J7 = CMP-0093483-1: RJ45 Connector with 1000 Base-TX Inetgrated Magnetic; Manufacturer: Link-PP; SizeZ_mm: 13.7mm; AEC Qualified: No; DUT-Pitch_mm: 1.27mm; Conn Gender: Female; Is Female: yes; ContactFinish: Gold; Conn Orientation: Horizontal
Q4-Q6 = CMP-0000947-2: MOSFET, N-CH, 100 V, 0.17 A, SOT-23; Alternate Manufacturer: None; Manufacturer: Fairchild Semiconductor; SizeZ_mm: 1.1; ChType: N; Value2: 1.8 nC; Value1: 1; VdsMax_V: 100V; SizeX_mm: 2.5; SizeY_mm: 3; Vgs_V: 20V; Value: 100V; Rdson45_ohm: 10; SizeArea_mm2: 7.5; AEC Category: Q101; IdsMax_A: 1.7dA; SizeAreaWB_mm2: 14; U/M: EA; QgTyp_nC: 1.8
R224 R226 R228 = CMP-0026878-3: RES, 220, 5%, 0.063 W, AEC-Q200 Grade 0, 0402; Manufacturer: Vishay-Dale; Power_W: 63mW; TempCo: 200 ppm/C; Value_Code: 220R; Value: 220; EIA_Code: E24; SizeX_mm: 1; SizeY_mm: 0.5; SizeZ_mm: 0.6; Value2: 0.063W; AEC Qualified: Y; VDC_V: 50V; AEC Category: Q200; AEC Grade: 0
R225 R227 R229 = CMP-0026992-3: as R100-R106 on sheet PROC171_Ehernet_PHY_1
R254 = CMP-0021522-3: RES, 1.00 M, 1%, 0.125 W, AEC-Q200 Grade 0, 0805; Manufacturer: Panasonic; Power_W: 125mW; TempCo: 100 ppm/C; Value_Code: 1M00; Value: 1.00Meg; EIA_Code: E96; Res_ohm: 1M; SizeX_mm: 2; SizeY_mm: 1.25; SizeZ_mm: 1.45; Value2: 0.125W; SizeArea_mm2: 2.5; AEC Qualified: Y; AEC Category: Q200; AEC Grade: 0; SizeAreaWB_mm2: 6.75
TP21 = CMP-0078143-3: TEST POINT.  No entry in BOM.
U38 U39 = CMP-0073613-3: 4-Channel Ultra-Low-Capacitance IEC ESD Protection Diode, DQA0010A (USON-10); Alternate Manufacturer: Texas Instruments; Green_Lifecycle: Active; SizeAreaWB_mm2: 7.0; Green_REACh: Passed; SizeZ_mm: 0.55; SizeX_mm: 1.0; SizeY_mm: 2.5; CompType: IC; AEC Category: Q200; AEC Qualified: N

## Sheet PROC171_XDS110_2.SchDoc: XDS110 JTAG/USB-to-UART Bridge
size 431 x 279 mm; Date: Not shown in title block; ApprovedBy: Not shown in title block; CheckedBy: Not shown in title block; Author: Not shown in title block; CompanyName: Not shown in title block; Engineer: Not shown in title block; Organization: Not shown in title block; Address1: Not shown in title block; Address2: Not shown in title block; Address3: Not shown in title block; Address4: Not shown in title block; DocumentNumber: 26; Revision: Use project parameter SCH_Rev; SheetNumber: 26; SheetTotal: 27; PageSetup: Record=PageOptions¦CenterHorizontal=True¦CenterVertical=True¦PrintScale=1.00¦XCorrection=1.00¦YCorrection=1.00¦PrintKind=0¦BorderSize=5000000¦LeftOffset=0¦BottomOffset=0¦Orientation=2¦PaperLength=1000¦PaperWidth=1000¦Scale=100¦PaperSource=15¦PrintQuality=600¦MediaType=1¦DitherType=10¦PaperKind=Letter¦PrintScaleMode=1
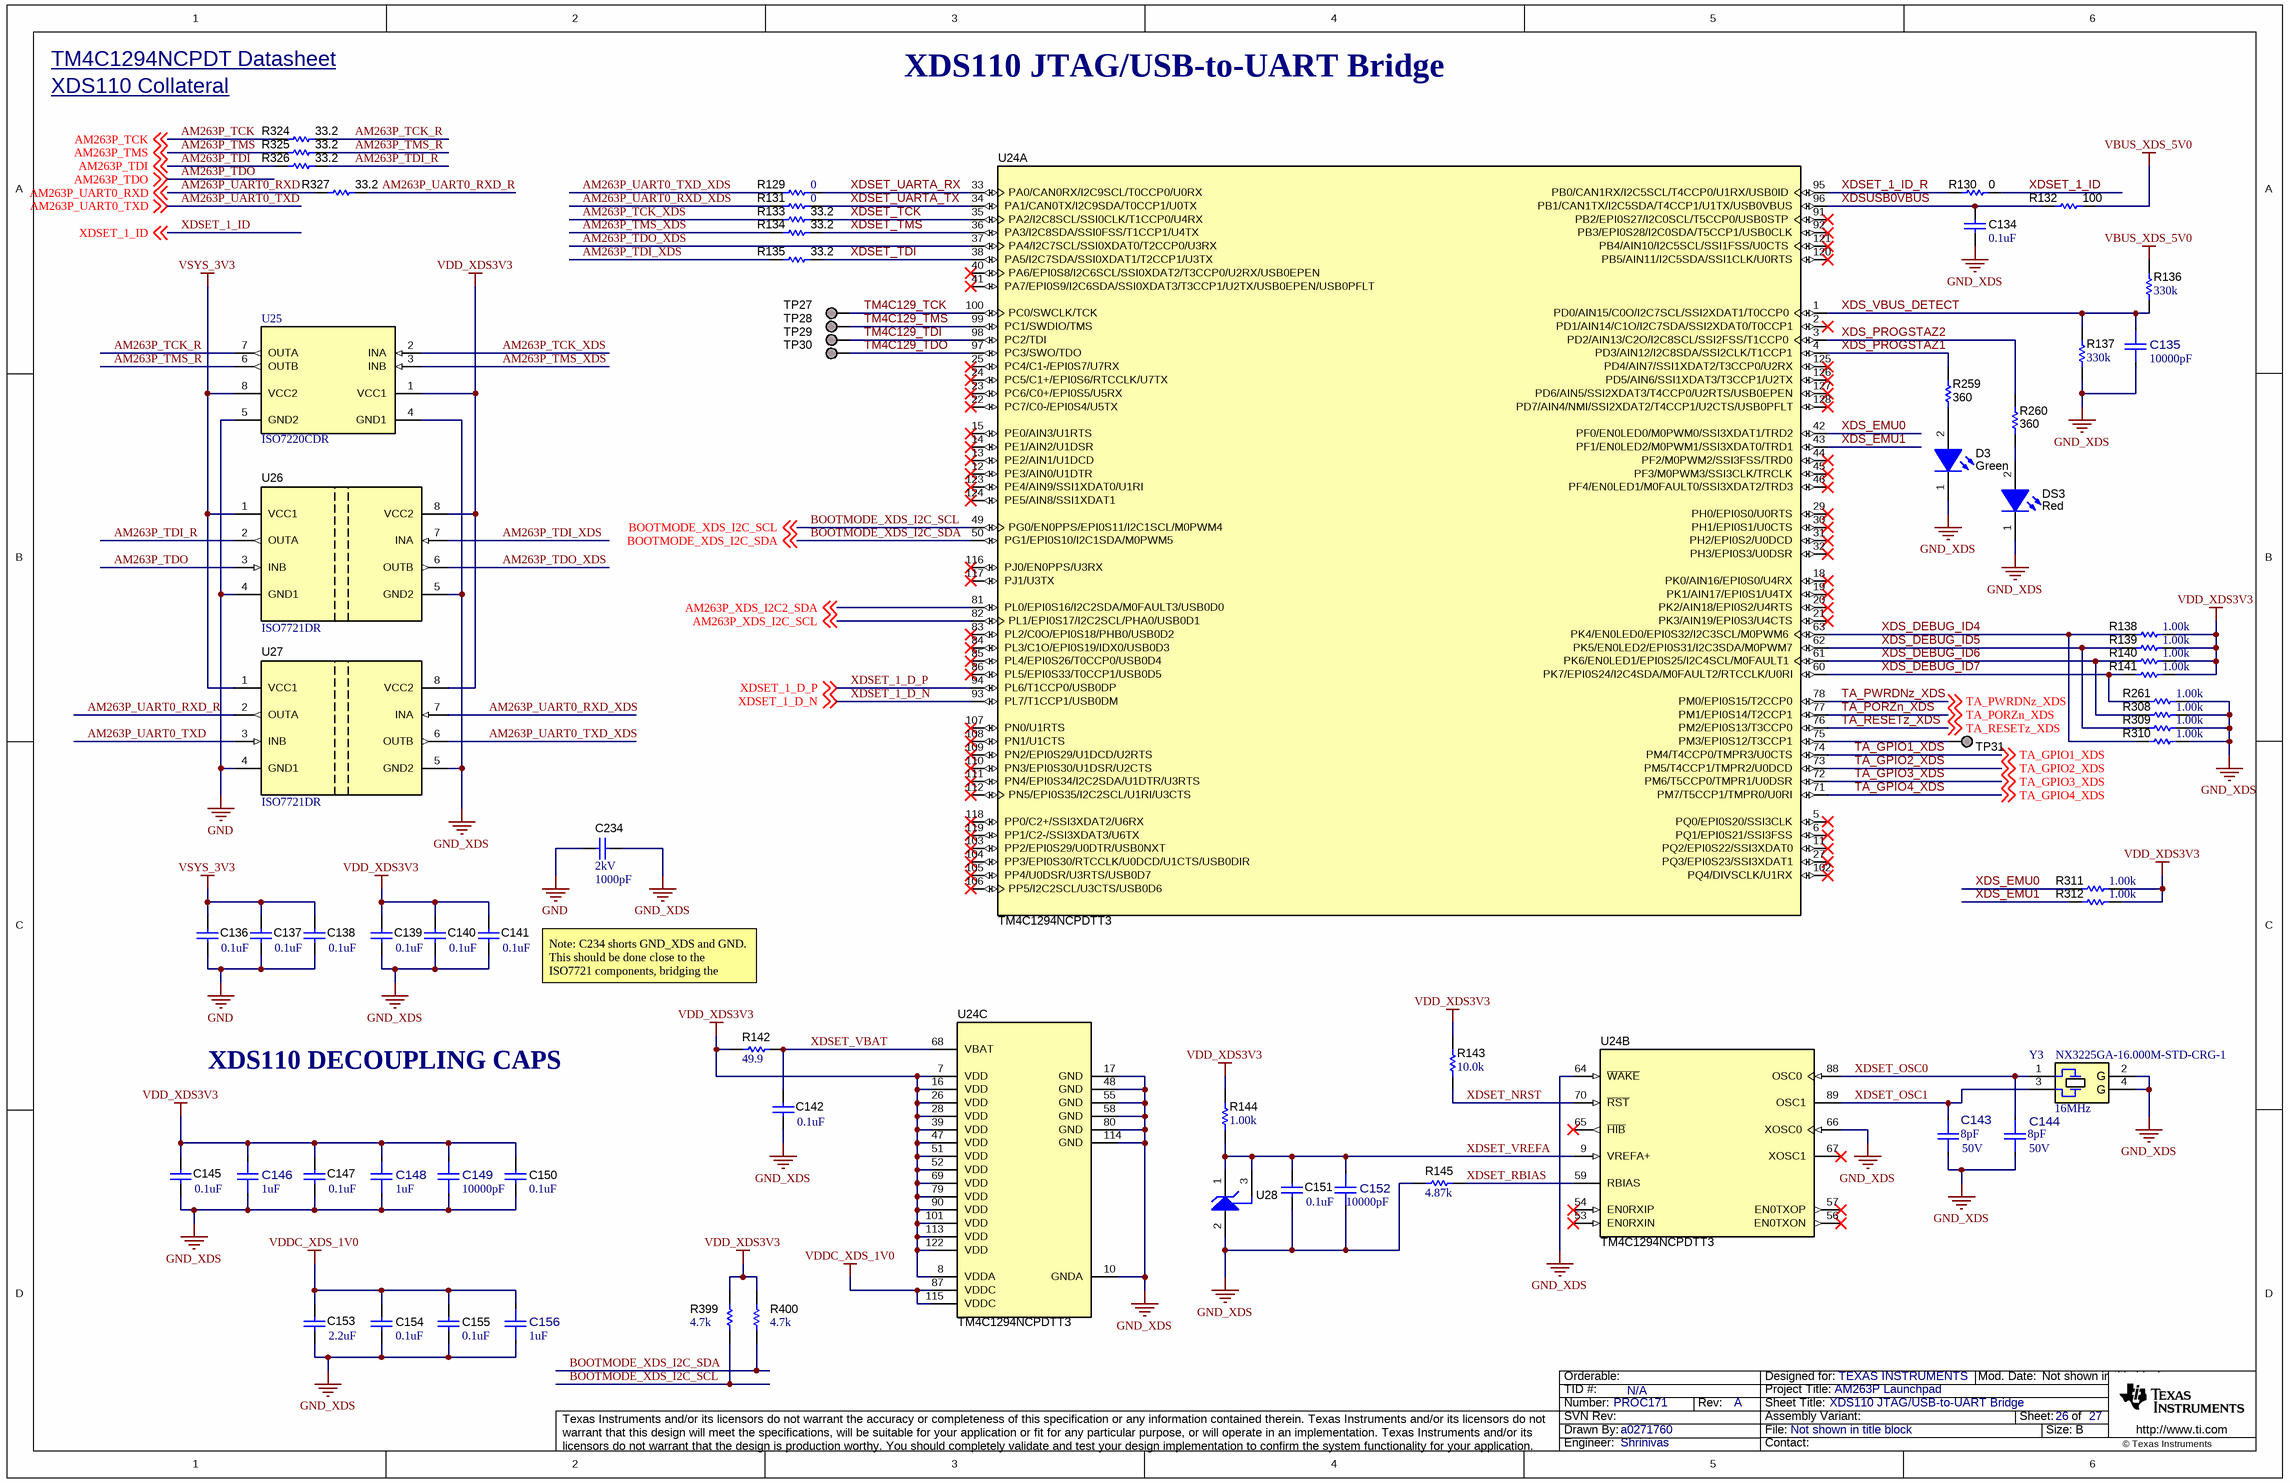
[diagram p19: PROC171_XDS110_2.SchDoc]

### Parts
C134  ValueDisplayed: 0.1uF  [0402]  (hidden comment: GRM155R71E104KE14D)
C135  ValueDisplayed: 10000pF  [FP-GRM1555C1E103JE01D_0402-MFG]  (hidden comment: GRM1555C1E103JE01D)
C136  ValueDisplayed: 0.1uF  [0402]  (hidden comment: GRM155R71E104KE14D)
C137  ValueDisplayed: 0.1uF  [0402]  (hidden comment: GRM155R71E104KE14D)
C138  ValueDisplayed: 0.1uF  [0402]  (hidden comment: GRM155R71E104KE14D)
C139  ValueDisplayed: 0.1uF  [0402]  (hidden comment: GRM155R71E104KE14D)
C140  ValueDisplayed: 0.1uF  [0402]  (hidden comment: GRM155R71E104KE14D)
C141  ValueDisplayed: 0.1uF  [0402]  (hidden comment: GRM155R71E104KE14D)
C142  ValueDisplayed: 0.1uF  [0402]  (hidden comment: GRM155R71E104KE14D)
C143  Cap_F: 8pF  VDC_V: 50V  [FP-GJM1555C1H8R0DB01D_0402-MFG]  (hidden comment: GJM1555C1H8R0DB01D)
C144  Cap_F: 8pF  VDC_V: 50V  [FP-GJM1555C1H8R0DB01D_0402-MFG]  (hidden comment: GJM1555C1H8R0DB01D)
C145  ValueDisplayed: 0.1uF  [0402]  (hidden comment: GRM155R71E104KE14D)
C146  ValueDisplayed: 1uF  [FP-GRM155C71A105KE11D_0402-MFG]  (hidden comment: GRM155C71A105KE11D)
C147  ValueDisplayed: 0.1uF  [0402]  (hidden comment: GRM155R71E104KE14D)
C148  ValueDisplayed: 1uF  [FP-GRM155C71A105KE11D_0402-MFG]  (hidden comment: GRM155C71A105KE11D)
C149  ValueDisplayed: 10000pF  [FP-GRM1555C1E103JE01D_0402-MFG]  (hidden comment: GRM1555C1E103JE01D)
C150  ValueDisplayed: 0.1uF  [0402]  (hidden comment: GRM155R71E104KE14D)
C151  ValueDisplayed: 0.1uF  [0402]  (hidden comment: GRM155R71E104KE14D)
C152  ValueDisplayed: 10000pF  [FP-GRM1555C1E103JE01D_0402-MFG]  (hidden comment: GRM1555C1E103JE01D)
C153  ValueDisplayed: 2.2uF  [0402]  (hidden comment: GRM155C81C225KE11D)
C154  ValueDisplayed: 0.1uF  [0402]  (hidden comment: GRM155R71E104KE14D)
C155  ValueDisplayed: 0.1uF  [0402]  (hidden comment: GRM155R71E104KE14D)
C156  ValueDisplayed: 1uF  [FP-GRM155C71A105KE11D_0402-MFG]  (hidden comment: GRM155C71A105KE11D)
C234  VDC_V: 2kV  ValueDisplayed: 1000pF  [1808]  (hidden comment: GR442QR73D102KW01L)
D3  value Green  [WL-SMCW_GREEN]  (hidden comment: 150060VS75000)
DS3  value Red  [WL-SMCW_RED]  (hidden comment: 150060RS75000)
R129  ValueDisplayed: 0  [0402]  (hidden comment: ERJ-2GE0R00X)
R130  ValueDisplayed: 0  [0402L]  (hidden comment: ERJ-2GE0R00X)
R131  ValueDisplayed: 0  [0402]  (hidden comment: ERJ-2GE0R00X)
R132  ValueDisplayed: 100  [0402L]  (hidden comment: ERJ-2GEJ101X)
R133  ValueDisplayed: 33.2  [0402]  (hidden comment: CRCW040233R2FKED)
R134  ValueDisplayed: 33.2  [0402]  (hidden comment: CRCW040233R2FKED)
R135  ValueDisplayed: 33.2  [0402]  (hidden comment: CRCW040233R2FKED)
R136  ValueDisplayed: 330k  [0402L]  (hidden comment: CRCW0402330KFKED)
R137  ValueDisplayed: 330k  [0402L]  (hidden comment: CRCW0402330KFKED)
R138  ValueDisplayed: 1.00k  [0402L]  (hidden comment: CRCW04021K00FKED)
R139  ValueDisplayed: 1.00k  [0402L]  (hidden comment: CRCW04021K00FKED)
R140  ValueDisplayed: 1.00k  [0402L]  (hidden comment: CRCW04021K00FKED)
R141  ValueDisplayed: 1.00k  [0402L]  (hidden comment: CRCW04021K00FKED)
R142  ValueDisplayed: 49.9  [0402L]  (hidden comment: CRCW040249R9FKED)
R143  ValueDisplayed: 10.0k  [0402L]  (hidden comment: CRCW040210K0FKED)
R144  ValueDisplayed: 1.00k  [0402L]  (hidden comment: CRCW04021K00FKED)
R145  ValueDisplayed: 4.87k  [0402L]  (hidden comment: CRCW04024K87FKED)
R259  ValueDisplayed: 360  [0402L]  (hidden comment: ERJ-2GEJ361X)
R260  ValueDisplayed: 360  [0402L]  (hidden comment: ERJ-2GEJ361X)
R261  ValueDisplayed: 1.00k  [0402L]  (hidden comment: CRCW04021K00FKED)
R308  ValueDisplayed: 1.00k  [0402L]  (hidden comment: CRCW04021K00FKED)
R309  ValueDisplayed: 1.00k  [0402L]  (hidden comment: CRCW04021K00FKED)
R310  ValueDisplayed: 1.00k  [0402L]  (hidden comment: CRCW04021K00FKED)
R311  ValueDisplayed: 1.00k  [0402L]  (hidden comment: CRCW04021K00FKED)
R312  ValueDisplayed: 1.00k  [0402L]  (hidden comment: CRCW04021K00FKED)
R324  ValueDisplayed: 33.2  [0402]  (hidden comment: CRCW040233R2FKED)
R325  ValueDisplayed: 33.2  [0402]  (hidden comment: CRCW040233R2FKED)
R326  ValueDisplayed: 33.2  [0402]  (hidden comment: CRCW040233R2FKED)
R327  ValueDisplayed: 33.2  [0402]  (hidden comment: CRCW040233R2FKED)
R399  ValueDisplayed: 4.7k  [0402]  (hidden comment: CRCW04024K70JNED)
R400  ValueDisplayed: 4.7k  [0402]  (hidden comment: CRCW04024K70JNED)
TP27  TESTPOINT  [TP_25MIL-SMT]  (value not drawn)  (no BOM)
TP28  TESTPOINT  [TP_25MIL-SMT]  (value not drawn)  (no BOM)
TP29  TESTPOINT  [TP_25MIL-SMT]  (value not drawn)  (no BOM)
TP30  TESTPOINT  [TP_25MIL-SMT]  (value not drawn)  (no BOM)
TP31  TESTPOINT  [TP_25MIL-SMT]  (value not drawn)  (no BOM)
U24  TM4C1294NCPDTT3  [PDT0128A]  (parts A,B,C of 3)
U25  ISO7220CDR  [D0008B_N]
U26  ISO7721DR  [D0008B_HV]
U27  ISO7721DR  [D0008B_HV]
U28  LM4040C25QDBZR  [DBZ0003A_N]  (value not drawn)
Y3  NX3225GA-16.000M-STD-CRG-1  Frequency_Fixed: 16MHz  [NDK_NX3225GA]

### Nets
GND: C136.1 C137.1 C138.1 C234.2 U25.5(GND2) U26.4(GND1) U27.4(GND1)
GND_XDS: C134.1 C135.2 C139.1 C140.1 C141.1 C142.2 C143.2 C144.2 C145.1 C146.1 C147.1 C148.1 C149.1 C150.1 C151.1 C152.2 C153.1 C154.1 C155.1 C156.1 C234.1 D3.1(K) DS3.1(K) R137.1 R145.1 R261.2 R308.2 R309.2 R310.2 U24.10(GNDA) U24.17(GND) U24.48(GND) U24.55(GND) U24.58(GND) U24.64(~{WAKE}) U24.66(XOSC0) U24.80(GND) U24.114(GND) U25.4(GND1) U26.5(GND2) U27.5(GND2) U28.2(ANODE) Y3.2(GND) Y3.4(GND)
VBUS_XDS_5V0: R132.2 R136.2
VDD_XDS3V3: C139.2 C140.2 C141.2 C145.2 C146.2 C147.2 C148.2 C149.2 C150.2 R138.2 R139.2 R140.2 R141.2 R142.2 R143.2 R144.2 R311.2 R312.2 R399.2 R400.2 U24.7(VDD) U24.8(VDDA) U24.16(VDD) U24.26(VDD) U24.28(VDD) U24.39(VDD) U24.47(VDD) U24.51(VDD) U24.52(VDD) U24.69(VDD) U24.79(VDD) U24.90(VDD) U24.101(VDD) U24.113(VDD) U24.122(VDD) U25.1(VCC1) U26.8(VCC2) U27.8(VCC2)
VDDC_XDS_1V0: C153.2 C154.2 C155.2 C156.2 U24.87(VDDC) U24.115(VDDC)
VSYS_3V3: C136.2 C137.2 C138.2 U25.8(VCC2) U26.1(VCC1) U27.1(VCC1)
AM263P_TCK: R324.1 ; off-sheet AM263P_TCK
AM263P_TCK_R: R324.2 U25.7(OUTA)
AM263P_TCK_XDS: R133.1 U25.2(INA)
AM263P_TDI: R326.1 ; off-sheet AM263P_TDI
AM263P_TDI_R: R326.2 U26.2(OUTA)
AM263P_TDI_XDS: R135.1 U26.7(INA)
AM263P_TDO: U26.3(INB) ; off-sheet AM263P_TDO
AM263P_TDO_XDS: U24.37(PA4/I2C7SCL/SSI0XDAT0/T2CCP0/U3RX) U26.6(OUTB)
AM263P_TMS: R325.1 ; off-sheet AM263P_TMS
AM263P_TMS_R: R325.2 U25.6(OUTB)
AM263P_TMS_XDS: R134.1 U25.3(INB)
AM263P_UART0_RXD: R327.1 ; off-sheet AM263P_UART0_RXD
AM263P_UART0_RXD_R: R327.2 U27.2(OUTA)
AM263P_UART0_RXD_XDS: R131.1 U27.7(INA)
AM263P_UART0_TXD: U27.3(INB) ; off-sheet AM263P_UART0_TXD
AM263P_UART0_TXD_XDS: R129.1 U27.6(OUTB)
AM263P_XDS_I2C2_SDA: U24.81(PL0/EPI0S16/I2C2SDA/M0FAULT3/USB0D0) ; off-sheet AM263P_XDS_I2C2_SDA
AM263P_XDS_I2C_SCL: U24.82(PL1/EPI0S17/I2C2SCL/PHA0/USB0D1) ; off-sheet AM263P_XDS_I2C_SCL
BOOTMODE_XDS_I2C_SCL: R399.1 U24.49(PG0/EN0PPS/EPI0S11/I2C1SCL/M0PWM4) ; off-sheet BOOTMODE_XDS_I2C_SCL
BOOTMODE_XDS_I2C_SDA: R400.1 U24.50(PG1/EPI0S10/I2C1SDA/M0PWM5) ; off-sheet BOOTMODE_XDS_I2C_SDA
TA_GPIO1_XDS: U24.74(PM4/T4CCP0/TMPR3/U0CTS) ; off-sheet TA_GPIO1_XDS
TA_GPIO2_XDS: U24.73(PM5/T4CCP1/TMPR2/U0DCD) ; off-sheet TA_GPIO2_XDS
TA_GPIO3_XDS: U24.72(PM6/T5CCP0/TMPR1/U0DSR) ; off-sheet TA_GPIO3_XDS
TA_GPIO4_XDS: U24.71(PM7/T5CCP1/TMPR0/U0RI) ; off-sheet TA_GPIO4_XDS
TA_PORZn_XDS: U24.77(PM1/EPI0S14/T2CCP1) ; off-sheet TA_PORZn_XDS
TA_PWRDNz_XDS: U24.78(PM0/EPI0S15/T2CCP0) ; off-sheet TA_PWRDNz_XDS
TA_RESETz_XDS: U24.76(PM2/EPI0S13/T3CCP0) ; off-sheet TA_RESETz_XDS
TM4C129_TCK: TP27.1 U24.100(PC0/SWCLK/TCK)
TM4C129_TDI: TP29.1 U24.98(PC2/TDI)
TM4C129_TDO: TP30.1 U24.97(PC3/SWO/TDO)
TM4C129_TMS: TP28.1 U24.99(PC1/SWDIO/TMS)
XDS_DEBUG_ID4: R138.1 R310.1 U24.63(PK4/EN0LED0/EPI0S32/I2C3SCL/M0PWM6)
XDS_DEBUG_ID5: R139.1 R309.1 U24.62(PK5/EN0LED2/EPI0S31/I2C3SDA/M0PWM7)
XDS_DEBUG_ID6: R140.1 R308.1 U24.61(PK6/EN0LED1/EPI0S25/I2C4SCL/M0FAULT1)
XDS_DEBUG_ID7: R141.1 R261.1 U24.60(PK7/EPI0S24/I2C4SDA/M0FAULT2/RTCCLK/U0RI)
XDS_EMU0: R311.1 U24.42(PF0/EN0LED0/M0PWM0/SSI3XDAT1/TRD2)
XDS_EMU1: R312.1 U24.43(PF1/EN0LED2/M0PWM1/SSI3XDAT0/TRD1)
XDS_PROGSTAZ1: R259.2 U24.4(PD3/AIN12/I2C8SDA/SSI2CLK/T1CCP1)
XDS_PROGSTAZ2: R260.2 U24.3(PD2/AIN13/C2O/I2C8SCL/SSI2FSS/T1CCP0)
XDS_VBUS_DETECT: C135.1 R136.1 R137.2 U24.1(PD0/AIN15/C0O/I2C7SCL/SSI2XDAT1/T0CCP0)
XDSET_1_D_N: U24.93(PL7/T1CCP1/USB0DM) ; off-sheet XDSET_1_D_N
XDSET_1_D_P: U24.94(PL6/T1CCP0/USB0DP) ; off-sheet XDSET_1_D_P
XDSET_1_ID: R130.1 ; off-sheet XDSET_1_ID
XDSET_1_ID_R: R130.2 U24.95(PB0/CAN1RX/I2C5SCL/T4CCP0/U1RX/USB0ID)
XDSET_NRST: R143.1 U24.70(~{RST})
XDSET_OSC0: C144.1 U24.88(OSC0) Y3.1
XDSET_OSC1: C143.1 U24.89(OSC1) Y3.3
XDSET_RBIAS: R145.2 U24.59(RBIAS)
XDSET_TCK: R133.2 U24.35(PA2/I2C8SCL/SSI0CLK/T1CCP0/U4RX)
XDSET_TDI: R135.2 U24.38(PA5/I2C7SDA/SSI0XDAT1/T2CCP1/U3TX)
XDSET_TMS: R134.2 U24.36(PA3/I2C8SDA/SSI0FSS/T1CCP1/U4TX)
XDSET_UARTA_RX: R129.2 U24.33(PA0/CAN0RX/I2C9SCL/T0CCP0/U0RX)
XDSET_UARTA_TX: R131.2 U24.34(PA1/CAN0TX/I2C9SDA/T0CCP1/U0TX)
XDSET_VBAT: C142.1 R142.1 U24.68(VBAT)
XDSET_VREFA: C151.2 C152.1 R144.1 U24.9(VREFA+) U28.1(CATHODE) U28.3(NC)
XDSUSB0VBUS: C134.2 R132.1 U24.96(PB1/CAN1TX/I2C5SDA/T4CCP1/U1TX/USB0VBUS)
NetD3_2: D3.2(A) R259.1
NetDS3_2: DS3.2(A) R260.1
NetTP31_1: TP31.1 U24.75(PM3/EPI0S12/T3CCP1)

Not connected (* = marked no-connect by the designer): U24 2(PD1/AIN14/C1O/I2C7SDA/SSI2XDAT0/T0CCP1)* 5(PQ0/EPI0S20/SSI3CLK)* 6(PQ1/EPI0S21/SSI3FSS)* 11(PQ2/EPI0S22/SSI3XDAT0)* 12(PE3/AIN0/U1DTR)* 13(PE2/AIN1/U1DCD)* 14(PE1/AIN2/U1DSR)* 15(PE0/AIN3/U1RTS)* 18(PK0/AIN16/EPI0S0/U4RX)* 19(PK1/AIN17/EPI0S1/U4TX)* 20(PK2/AIN18/EPI0S2/U4RTS)* 21(PK3/AIN19/EPI0S3/U4CTS)* 22(PC7/C0-/EPI0S4/U5TX)* 23(PC6/C0+/EPI0S5/U5RX)* 24(PC5/C1+/EPI0S6/RTCCLK/U7TX)* 25(PC4/C1-/EPI0S7/U7RX)* 27(PQ3/EPI0S23/SSI3XDAT1)* 29(PH0/EPI0S0/U0RTS)* 30(PH1/EPI0S1/U0CTS)* 31(PH2/EPI0S2/U0DCD)* 32(PH3/EPI0S3/U0DSR)* 40(PA6/EPI0S8/I2C6SCL/SSI0XDAT2/T3CCP0/U2RX/USB0EPEN)* 41(PA7/EPI0S9/I2C6SDA/SSI0XDAT3/T3CCP1/U2TX/USB0EPEN/USB0PFLT)* 44(PF2/M0PWM2/SSI3FSS/TRD0)* 45(PF3/M0PWM3/SSI3CLK/TRCLK)* 46(PF4/EN0LED1/M0FAULT0/SSI3XDAT2/TRD3)* 53(EN0RXIN)* 54(EN0RXIP)* 56(EN0TXON)* 57(EN0TXOP)* 65(~{HIB})* 67(XOSC1)* 83(PL2/C0O/EPI0S18/PHB0/USB0D2)* 84(PL3/C1O/EPI0S19/IDX0/USB0D3)* 85(PL4/EPI0S26/T0CCP0/USB0D4)* 86(PL5/EPI0S33/T0CCP1/USB0D5)* 91(PB2/EPI0S27/I2C0SCL/T5CCP0/USB0STP)* 92(PB3/EPI0S28/I2C0SDA/T5CCP1/USB0CLK)* 102(PQ4/DIVSCLK/U1RX)* 103(PP2/EPI0S29/U0DTR/USB0NXT)* 104(PP3/EPI0S30/RTCCLK/U0DCD/U1CTS/USB0DIR)* 105(PP4/U0DSR/U3RTS/USB0D7)* 106(PP5/I2C2SCL/U3CTS/USB0D6)* 107(PN0/U1RTS)* 108(PN1/U1CTS)* 109(PN2/EPI0S29/U1DCD/U2RTS)* 110(PN3/EPI0S30/U1DSR/U2CTS)* 111(PN4/EPI0S34/I2C2SDA/U1DTR/U3RTS)* 112(PN5/EPI0S35/I2C2SCL/U1RI/U3CTS)* 116(PJ0/EN0PPS/U3RX)* 117(PJ1/U3TX)* 118(PP0/C2+/SSI3XDAT2/U6RX)* 119(PP1/C2-/SSI3XDAT3/U6TX)* 120(PB5/AIN11/I2C5SDA/SSI1CLK/U0RTS)* 121(PB4/AIN10/I2C5SCL/SSI1FSS/U0CTS)* 123(PE4/AIN9/SSI1XDAT0/U1RI)* 124(PE5/AIN8/SSI1XDAT1)* 125(PD4/AIN7/SSI1XDAT2/T3CCP0/U2RX)* 126(PD5/AIN6/SSI1XDAT3/T3CCP1/U2TX)* 127(PD6/AIN5/SSI2XDAT3/T4CCP0/U2RTS/USB0EPEN)* 128(PD7/AIN4/NMI/SSI2XDAT2/T4CCP1/U2CTS/USB0PFLT)*

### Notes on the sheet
- XDS110 Collateral <https://software-dl.ti.com/ccs/esd/documents/xdsdebugprobes/emu_xds110.html>
- TM4C1294NCPDT Datasheet <http://www.ti.com/lit/ds/symlink/tm4c1294ncpdt.pdf>
- XDS110 JTAG/USB-to-UART Bridge
- Note: C234 shorts GND_XDS and GND. This should be done close to the ISO7721 components, bridging the air-gap between the two portions of the PCB
- XDS110 DECOUPLING CAPS

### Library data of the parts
C134 C136-C142 C145 C147 C150 C151 C154 C155 = CMP-0006659-2: as C240-C242 on sheet PROC171_Ehernet_PHY_1
C135 C149 C152 = CMP-0035343-1: as C115 on sheet PROC171_Ehernet_PHY_1
C143 C144 = CMP-0035284-1: Multi-Layer Ceramic Capacitor 8pF C0G  ±0.5pF 0402 Paper T/R; Manufacturer: Murata; TempCo: 30ppm/°C; AEC Qualified: No; SizeZ_mm: 0.55mm
C146 C148 C156 = CMP-0035346-1: 1µF ±10% 10V Ceramic Capacitor X7S 0402 (1005 Metric); Manufacturer: Murata; TempCo: 22%; SizeZ_mm: 0.6mm; AEC Qualified: No
C153 = CMP-0006526-2: CAP, CERM, 2.2 uF, 16 V, +/- 10%, X6S, 0402; Manufacturer: MuRata; TaMin_C: -55°C; Polarized: N; SizeAreaWB_mm2: 3; Value1: Unknown; U/M: EA; Value: 2.2uF; TaMax_C: 105°C; SizeZ_mm: 0.6; SizeX_mm: 1; SizeY_mm: 0.5; Value2: 16V; Cap_F: 2.2µF; AEC Category: Q200
C234 = CMP-0009436-2: as C235 on sheet PROC171_Ehernet_RJ45_1
D3 = CMP-0002894-2: LED, Green, SMD; Manufacturer: Wurth Elektronik; Io_A: 20mA; Value1: W; Vf_V: 2V; Type: AlInGaP
DS3 = CMP-0002947-3: LED, Red, SMD; Manufacturer: Wurth Elektronik; Value1: 0.072W; Vf_V: 2V; Angle: 140; Tjmax_C: 85°C; Type: AlInGaP; Vr_V: 5V; Io_A: 30mA; Power_TotalModule: 72mW
R129 R131 = CMP-0026992-3: RES, 0, 5%, 0.1 W, AEC-Q200 Grade 0, 0402; Manufacturer: Panasonic; Power_W: 100mW; TempCo: 600 ppm/C; Value_Code: 0000; Value: 0; EIA_Code: E24; SizeX_mm: 1; SizeY_mm: 0.5; SizeZ_mm: 0.6; Value2: 0.1W; CompType: Resistor; AEC Qualified: Y; VDC_V: 50V; AEC Category: Q200; SizeAreaWB_mm2: 3; INSTALLATION: DNP
R130 = CMP-0026992-3: as R100-R106 on sheet PROC171_Ehernet_PHY_1
R132 = CMP-0026993-2: RES, 100, 5%, 0.1 W, AEC-Q200 Grade 0, 0402; Manufacturer: Panasonic; Power_W: 100mW; TempCo: 200 ppm/C; Value_Code: 100R; U/M: EA; Value: 100; EIA_Code: E24; SizeX_mm: 1; SizeY_mm: 0.5; SizeZ_mm: 0.6; Value2: 0.1W; AEC Qualified: Y; AEC Grade: 0; AEC Category: Q200
R133-R135 R324-R327 = CMP-0026299-2: RES, 33.2, 1%, 0.063 W, AEC-Q200 Grade 0, 0402; Manufacturer: Vishay-Dale; Power_W: 63mW; TempCo: 100 ppm/C; Value_Code: 33R2; Value: 33.2; EIA_Code: E96; SizeX_mm: 1; SizeY_mm: 0.5; SizeZ_mm: 0.6; Value2: 0.063W; AEC Qualified: Y; VDC_V: 50V; AEC Category: Q200; AEC Grade: 0
R136 R137 = CMP-0078210-2: RES, 330 k, 1%, 0.063 W, AEC-Q200 Grade 0, 0402; Manufacturer: Vishay-Dale; SizeArea_mm2: 0.5; AEC Qualified: Y; AEC Category: Q200; Value: 330k; SizeZ_mm: 0.6; TempCo: 100 ppm/C; AEC Grade: 0; Power_W: 63mW; VDC_V: 50V; Value2: 0.063W; SizeX_mm: 1
R138-R141 R144 R261 R308-R312 = CMP-0026071-3: RES, 1.00 k, 1%, 0.063 W, AEC-Q200 Grade 0, 0402; Manufacturer: Vishay-Dale; Power_W: 63mW; TempCo: 100 ppm/C; Value_Code: 1k00; Value: 1.00k; EIA_Code: E96; Res_ohm: 1k; SizeX_mm: 1; SizeY_mm: 0.5; SizeZ_mm: 0.6; Value2: 0.063W; AEC Qualified: Y; VDC_V: 50V; AEC Category: Q200; AEC Grade: 0
R142 = CMP-0026404-2: RES, 49.9, 1%, 0.063 W, AEC-Q200 Grade 0, 0402; Manufacturer: Vishay-Dale; Power_W: 63mW; TempCo: 100 ppm/C; Value_Code: 49R9; Value: 49.9; EIA_Code: E96; SizeX_mm: 1; SizeY_mm: 0.5; SizeZ_mm: 0.6; Value2: 0.063W; AEC Qualified: Y; VDC_V: 50V; AEC Category: Q200; AEC Grade: 0
R143 = CMP-0025958-3: as R425 on sheet PROC171_Ehernet_PHY_1
R145 = CMP-0026413-2: RES, 4.87 k, 1%, 0.063 W, AEC-Q200 Grade 0, 0402; Manufacturer: Vishay-Dale; Power_W: 63mW; TempCo: 100 ppm/C; Value_Code: 4k87; Value: 4.87k; EIA_Code: E96; SizeX_mm: 1; SizeY_mm: 0.5; SizeZ_mm: 0.6; Value2: 0.063W; AEC Qualified: Y; VDC_V: 50V; AEC Category: Q200; AEC Grade: 0
R259 R260 = CMP-0078194-1: RES, 360, 5%, 0.1 W, AEC-Q200 Grade 0, 0402; Manufacturer: Panasonic; Value_Code: 360R; SizeArea_mm2: 0.5; AEC Qualified: Y; AEC Category: Q200; Value: 360; SizeZ_mm: 0.6; EIA_Code: E24; TempCo: 200 ppm/C; AEC Grade: 0; Power_W: 100mW; VDC_V: 50V; Value2: 0.1W; U/M: EA; SizeX_mm: 1
R399 R400 = CMP-0026938-5: RES, 4.7 k, 5%, 0.063 W, AEC-Q200 Grade 0, 0402; Manufacturer: Vishay-Dale; Power_W: 63mW; TempCo: 200 ppm/C; Value_Code: 4k70; Value: 4.7k; EIA_Code: E24; SizeX_mm: 1; SizeY_mm: 0.5; SizeZ_mm: 0.6; Value2: 0.063W; AEC Qualified: Y; VDC_V: 50V; AEC Category: Q200; AEC Grade: 0
TP27-TP31 = CMP-0078143-3: TEST POINT.  No entry in BOM.
U24 = CMP-0029856-2: Tiva C Series Microcontroller, 1024 KB Flash, 256 KB SRAM, 12 Bit, 20 Channels, -40 to 105 degC, 128-Pin TQFP (PDT), Green (RoHS & no Sb/Br), Tray; Manufacturer: Texas Instruments; ADC Channels: 20; CPU: ARM Cortex-M4; Flash: 1024 KB; ADC Resolution: 12 Bits; Max Speed: 120 MHz; SRAM: 256 KB; SizeAreaWB_mm2: 324.0; SizeArea_mm2: 256.0; SizeX_mm: 16.0; SizeZ_mm: 1.2; CompType: IC
U25 = CMP-0029369-1: 25 Mbps Dual Channels, 2 / 0, Digital Isolator, 3.3 V / 5 V, -40 to +125 degC, 8-pin SOIC (D), Green (RoHS & no Sb/Br); Manufacturer: Texas Instruments; Supply Voltage(s)(V): 3.3, 5; Prop Delay(Max)(ns): 42; Insulation Rating(VRMS): 2500; Datarate(Mbps): 25; TTL/CMOS Input Threshold: TTL; Rating: Catalog; Input Noise Filter: Yes
U26 U27 = CMP-0076059-2: High Speed, Robust EMC Dual-Channel Digital Isolator, D0008B (SOIC-8); Manufacturer: Texas Instruments; SizeY_mm: 4.9; SizeArea_mm2: 29.4; Rating: Catalog; CompType: IC; AEC Category: Q200; AEC Qualified: N; SizeZ_mm: 1.75; SizeAreaWB_mm2: 55.2; SizeX_mm: 6.0
U28 = CMP-0033001-1: Precision Micropower Shunt Voltage Reference, 0.5% accuracy, 2.5 V, 15 ppm / degC, 15 mA, -40 to 125 degC, 3-pin SOT-23 (DBZ), Green (RoHS & no Sb/Br); Manufacturer: Texas Instruments; Initial Accuracy @ 25/deg C(%): 0.5; Temp Coeff(Typ)(ppm/ degree C): 15; Temp Coeff(Max)(ppm/ degree C): 100; Rating: Catalog; Min Iz for Regulation(uA): 75; VO(V): 2.5
Y3 = CMP-0004635-3: Crystal, 16 MHz, 8pF, SMD; Manufacturer: NDK; TaMax_C: 70°C; TaMin_C: -10°C; Frequency Stability: +/-30ppm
